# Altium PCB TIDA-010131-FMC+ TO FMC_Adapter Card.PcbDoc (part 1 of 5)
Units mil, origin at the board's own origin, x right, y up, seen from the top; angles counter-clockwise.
Board outline 2874.02 x 2362.2 mil, 12 copper layers (L1_Top Layer, L2_GND, L3_GND, L4_Signal layer1, L5_GND, L6_Signal Layer2, L7_GND, L8_Signal Layer3, L9_GND, L10_Signal Layer4, L11_GND, L12_Bottom Layer), stack 65.6 mil thick; 64 components, 219 nets, 2252 pads, 791 vias.
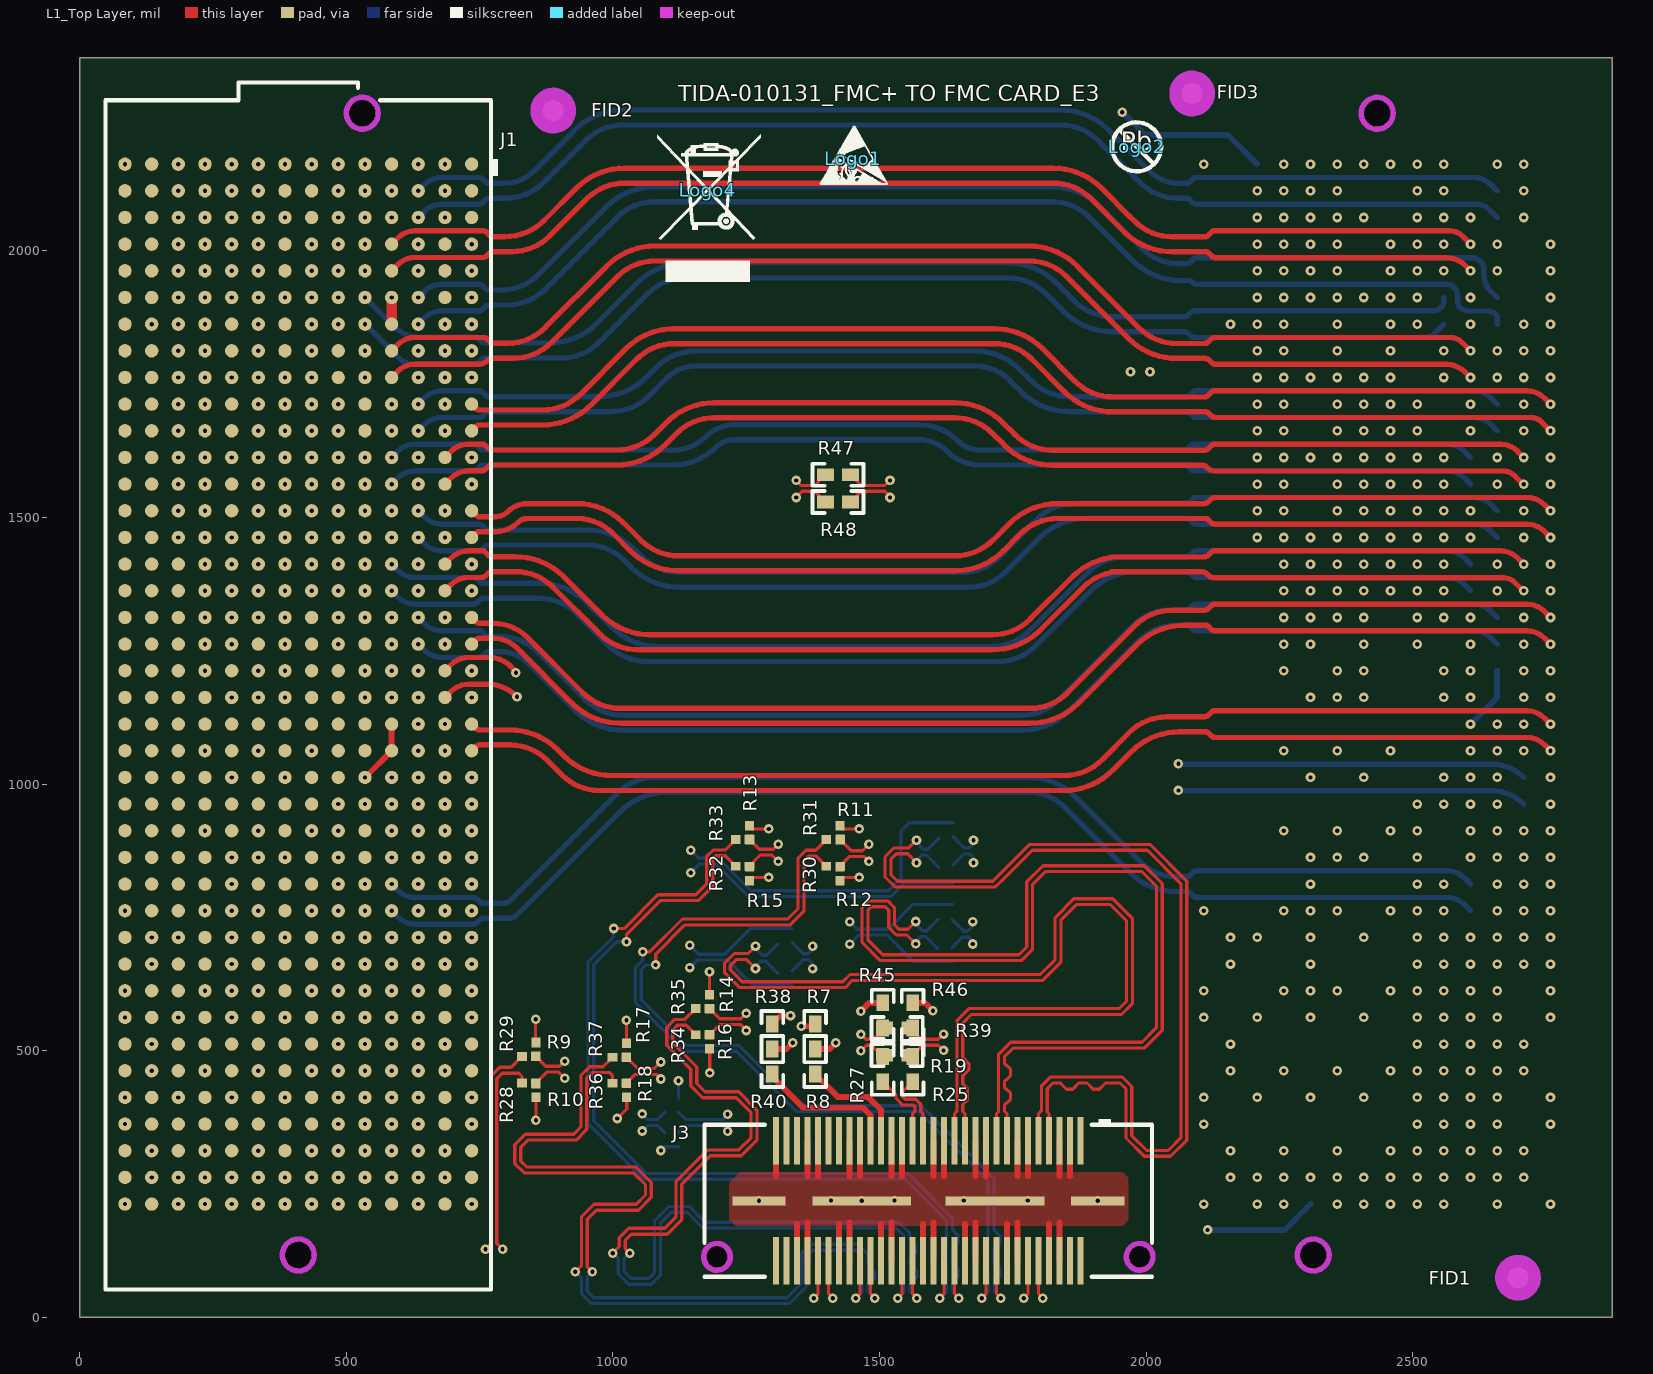
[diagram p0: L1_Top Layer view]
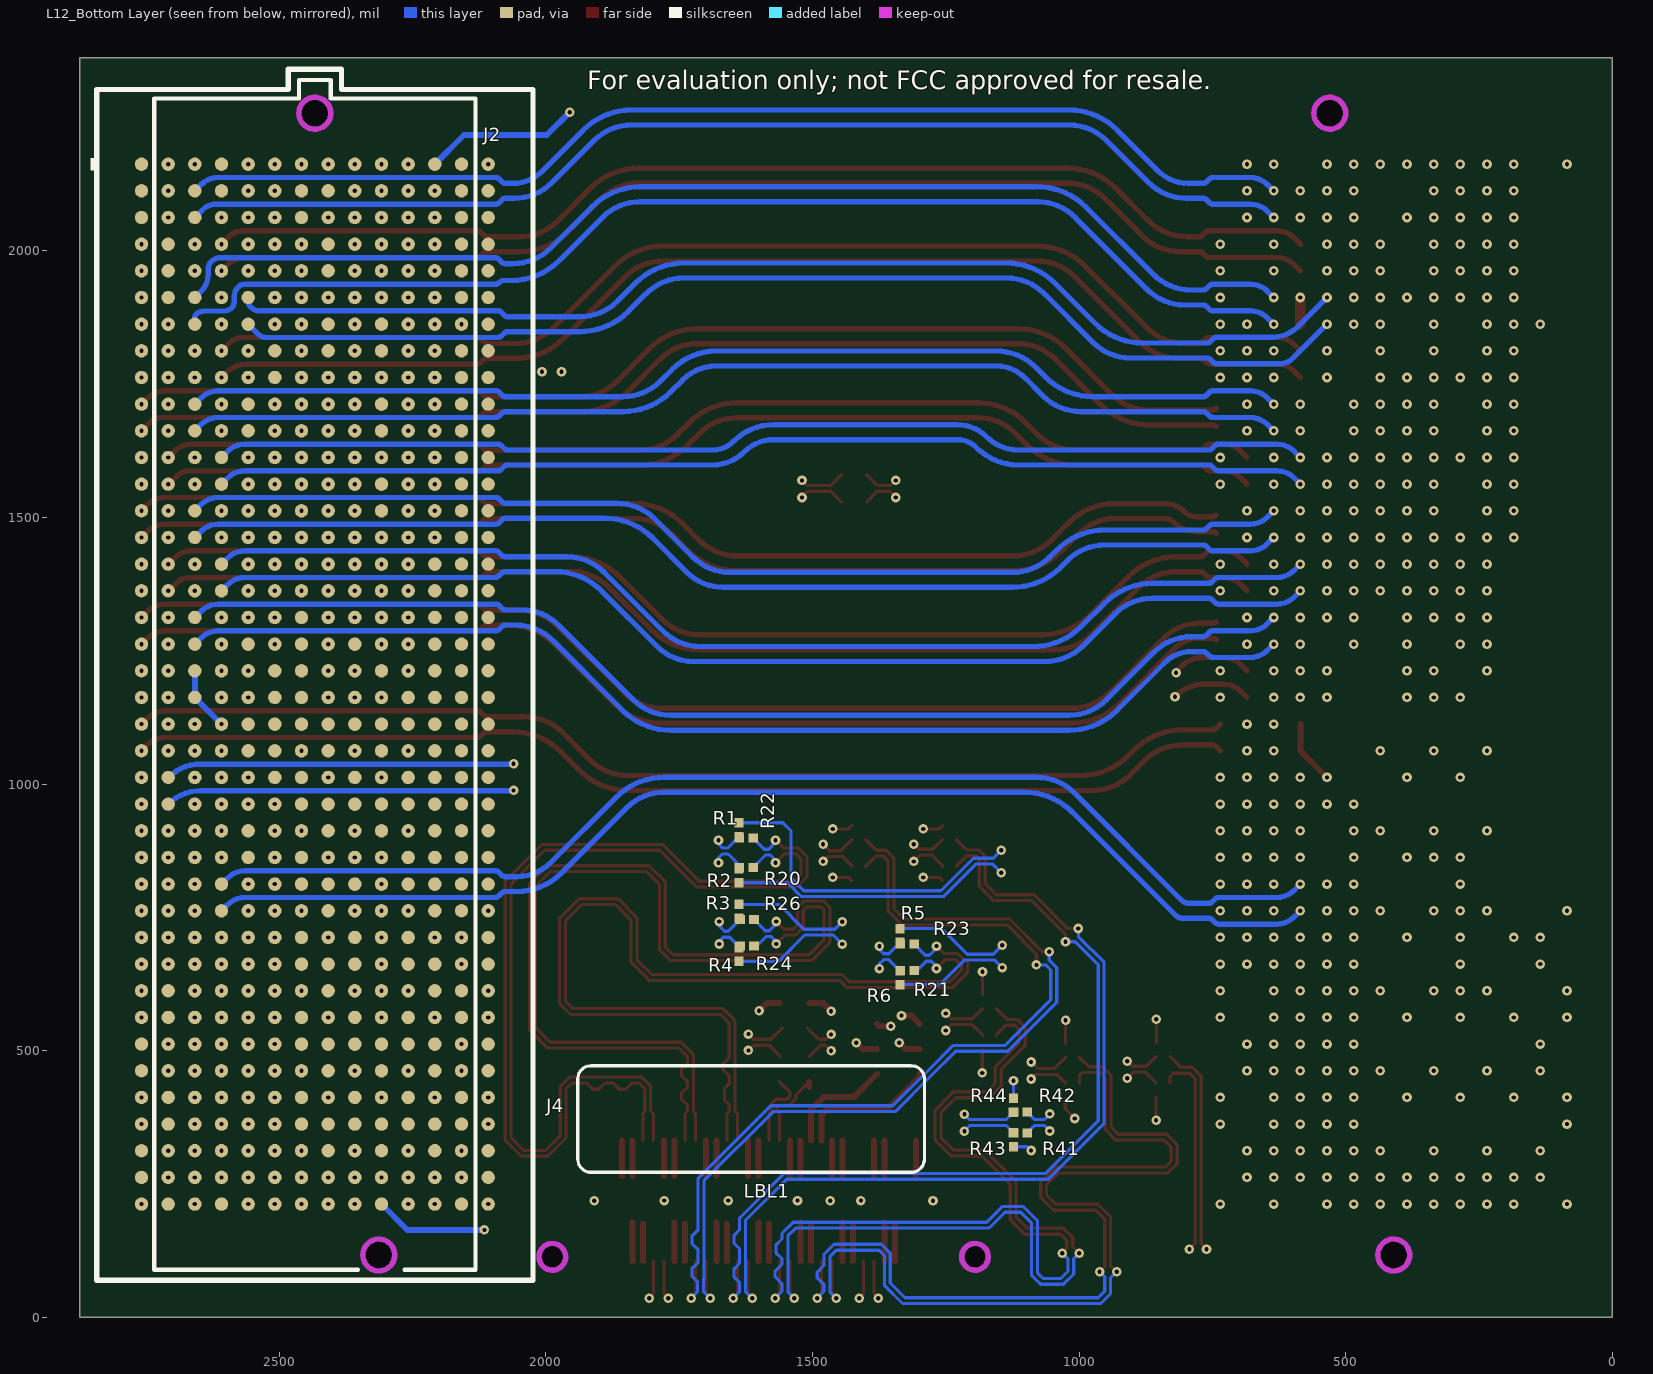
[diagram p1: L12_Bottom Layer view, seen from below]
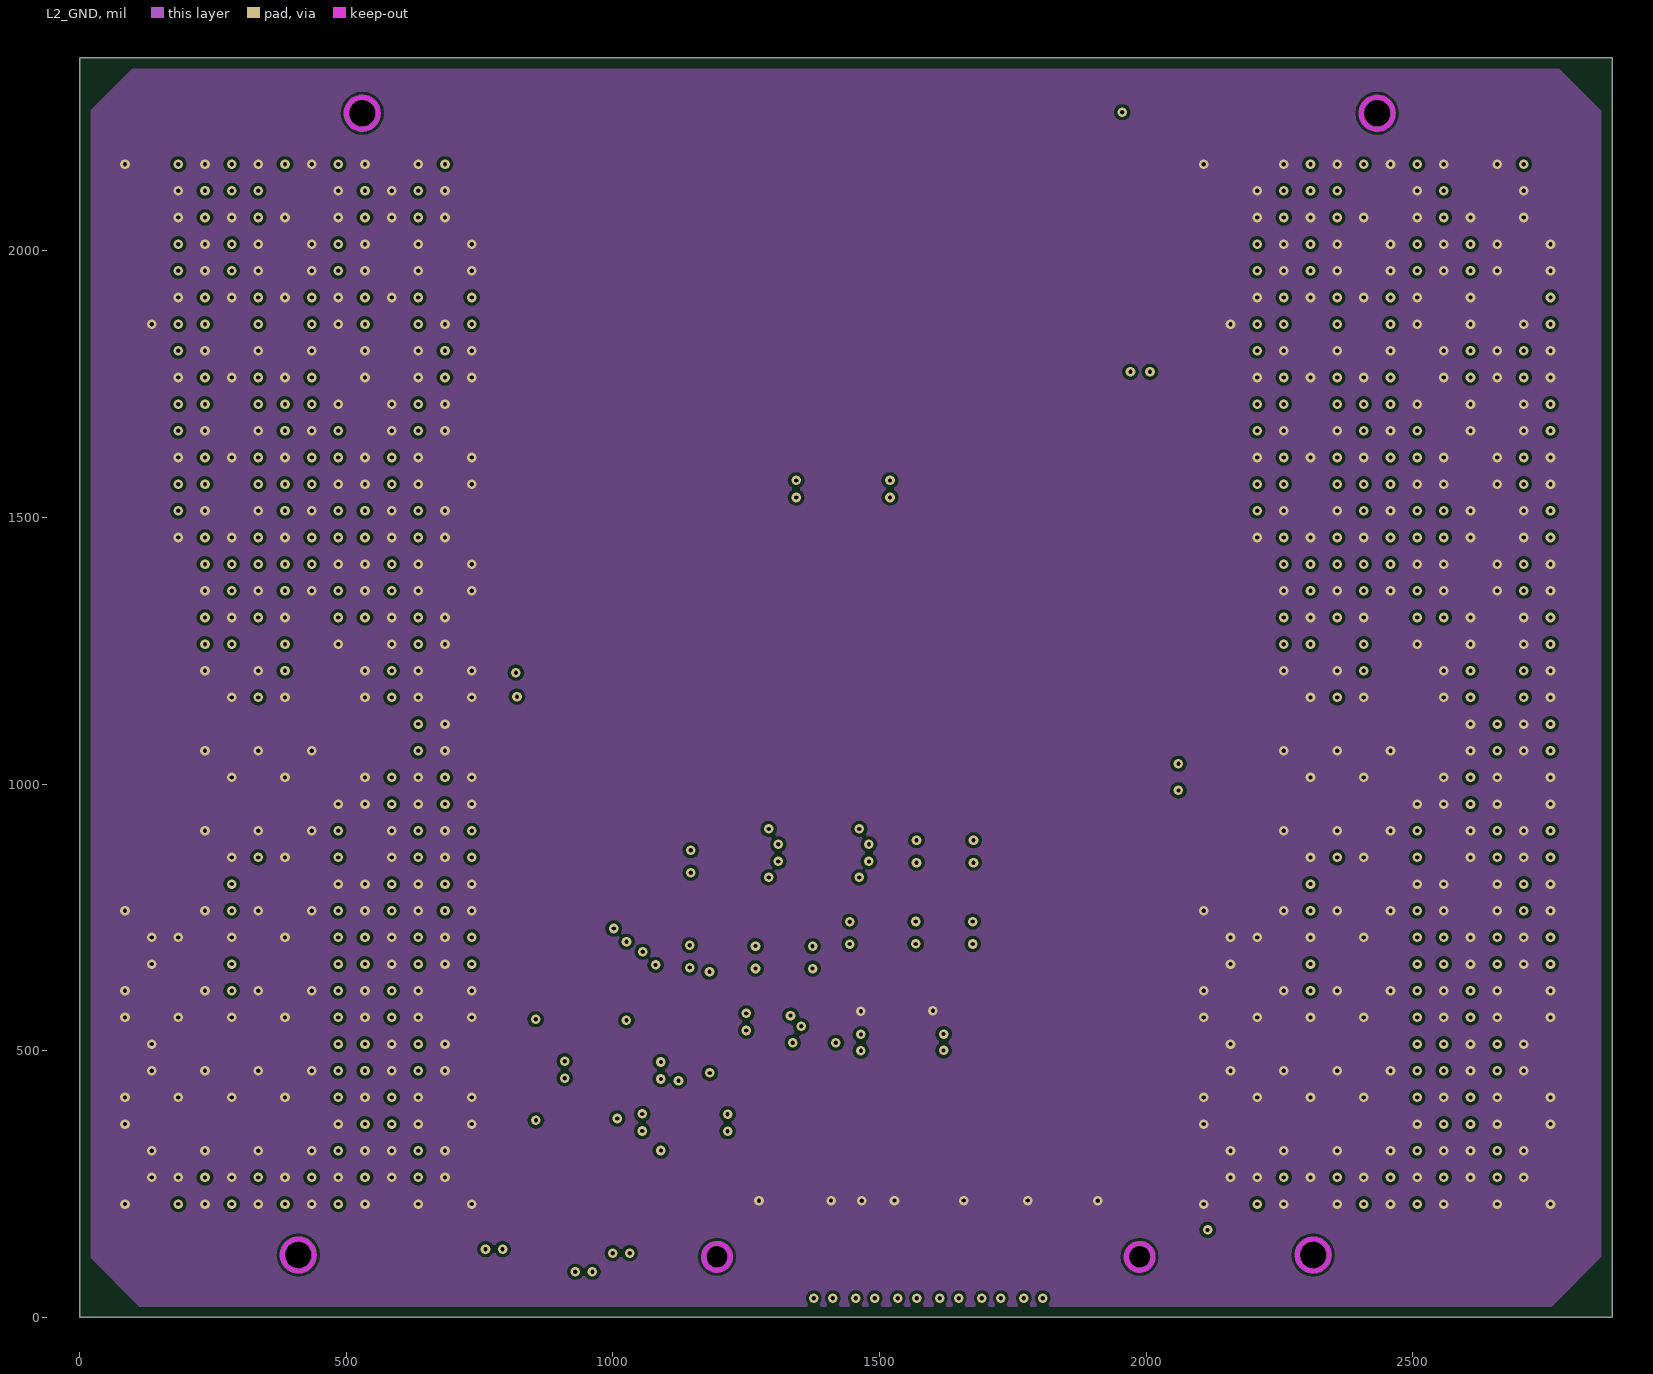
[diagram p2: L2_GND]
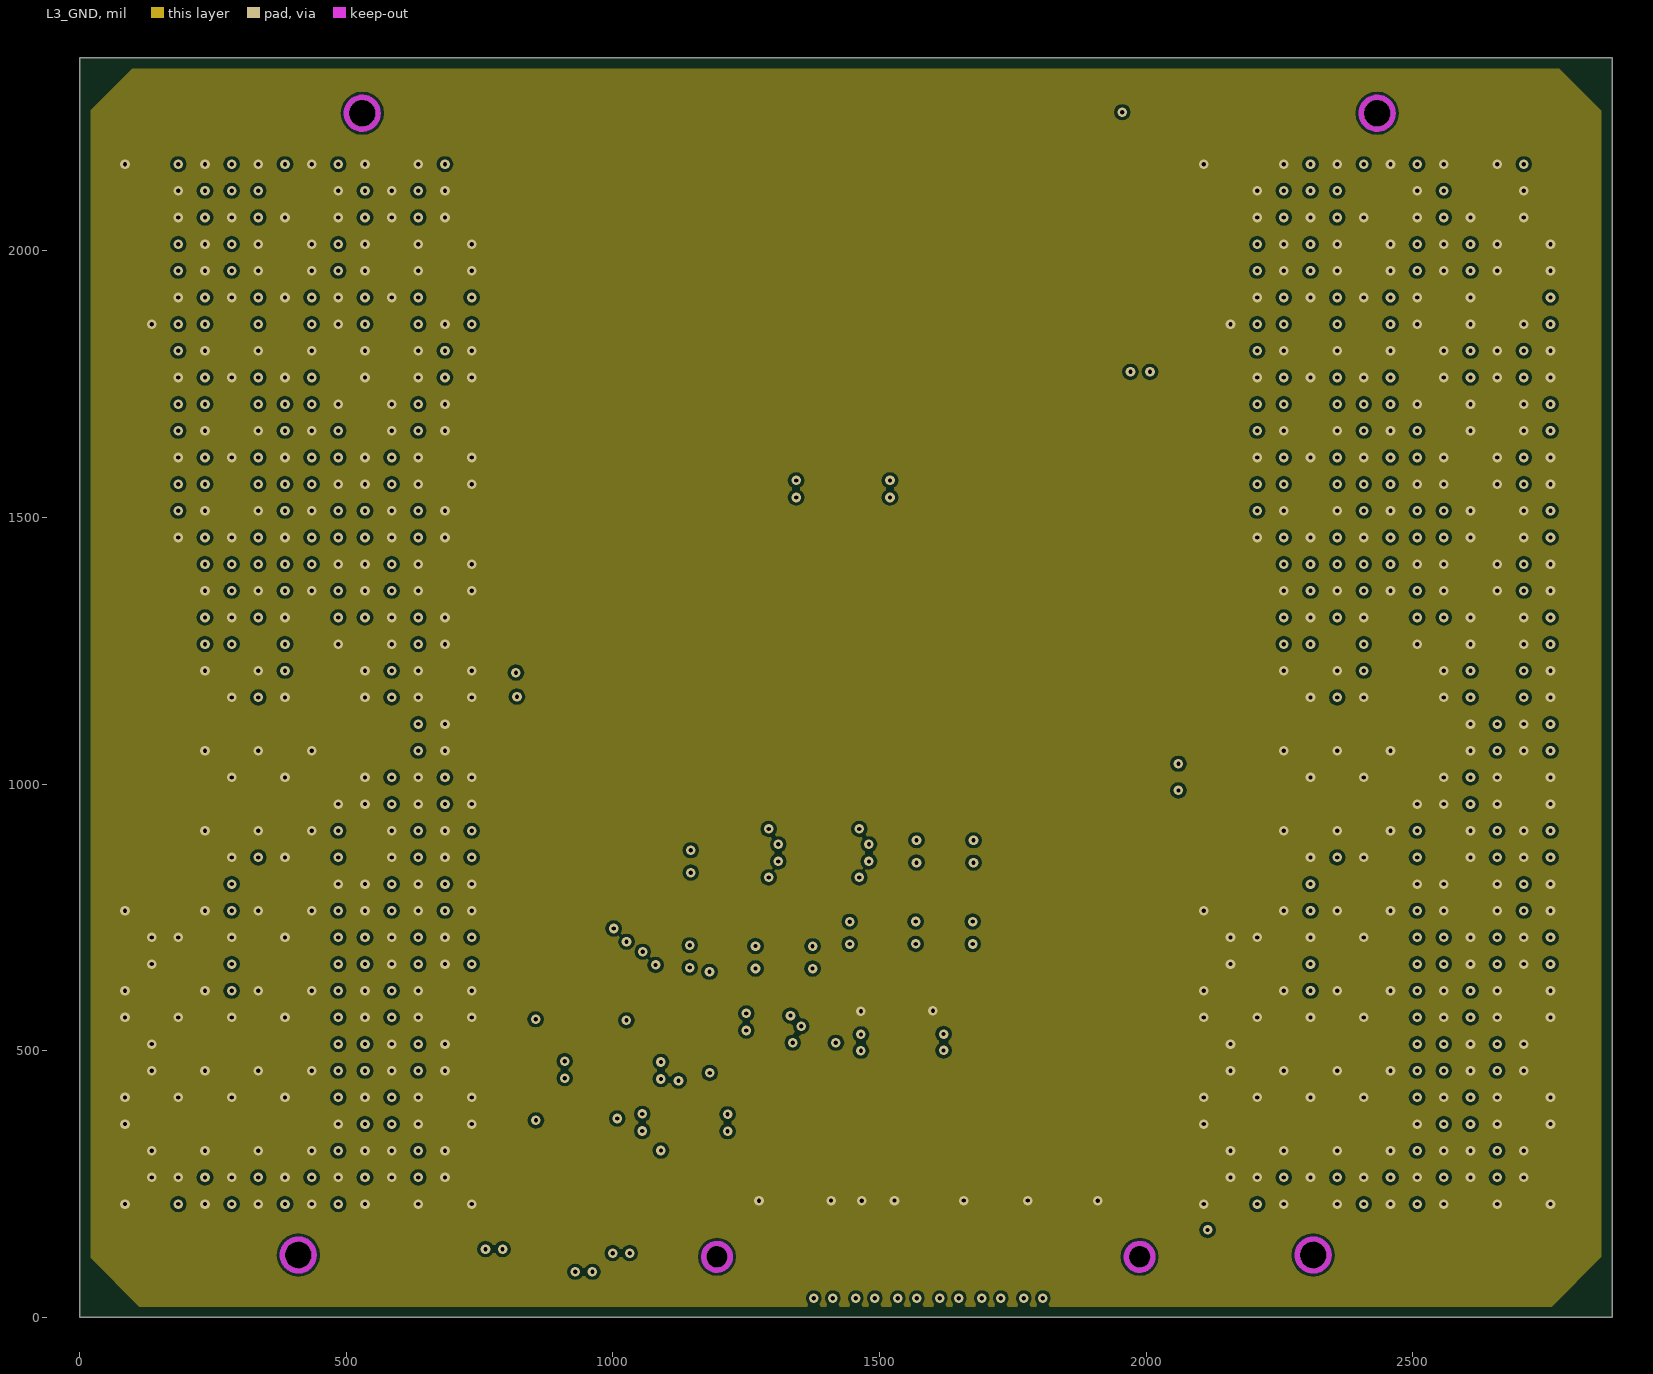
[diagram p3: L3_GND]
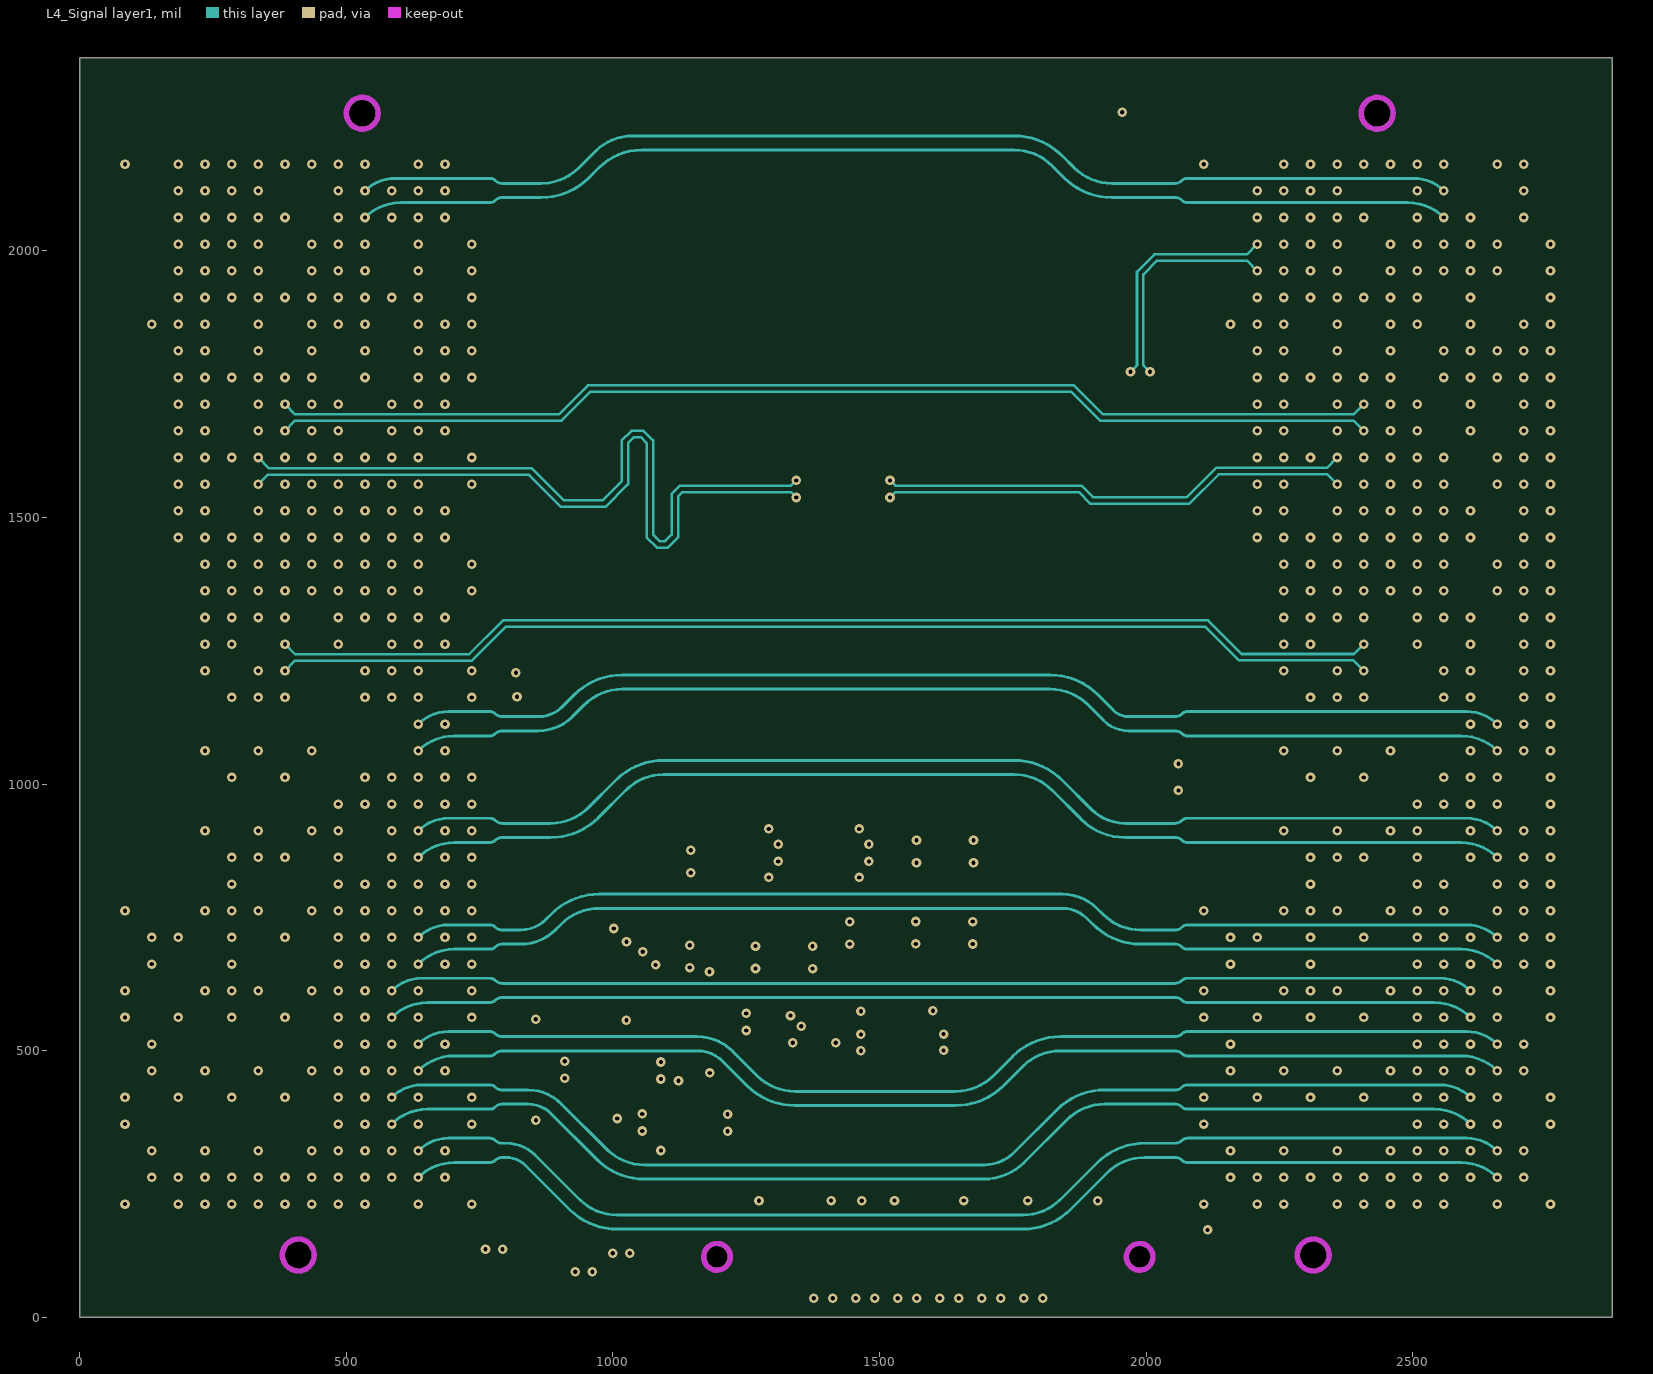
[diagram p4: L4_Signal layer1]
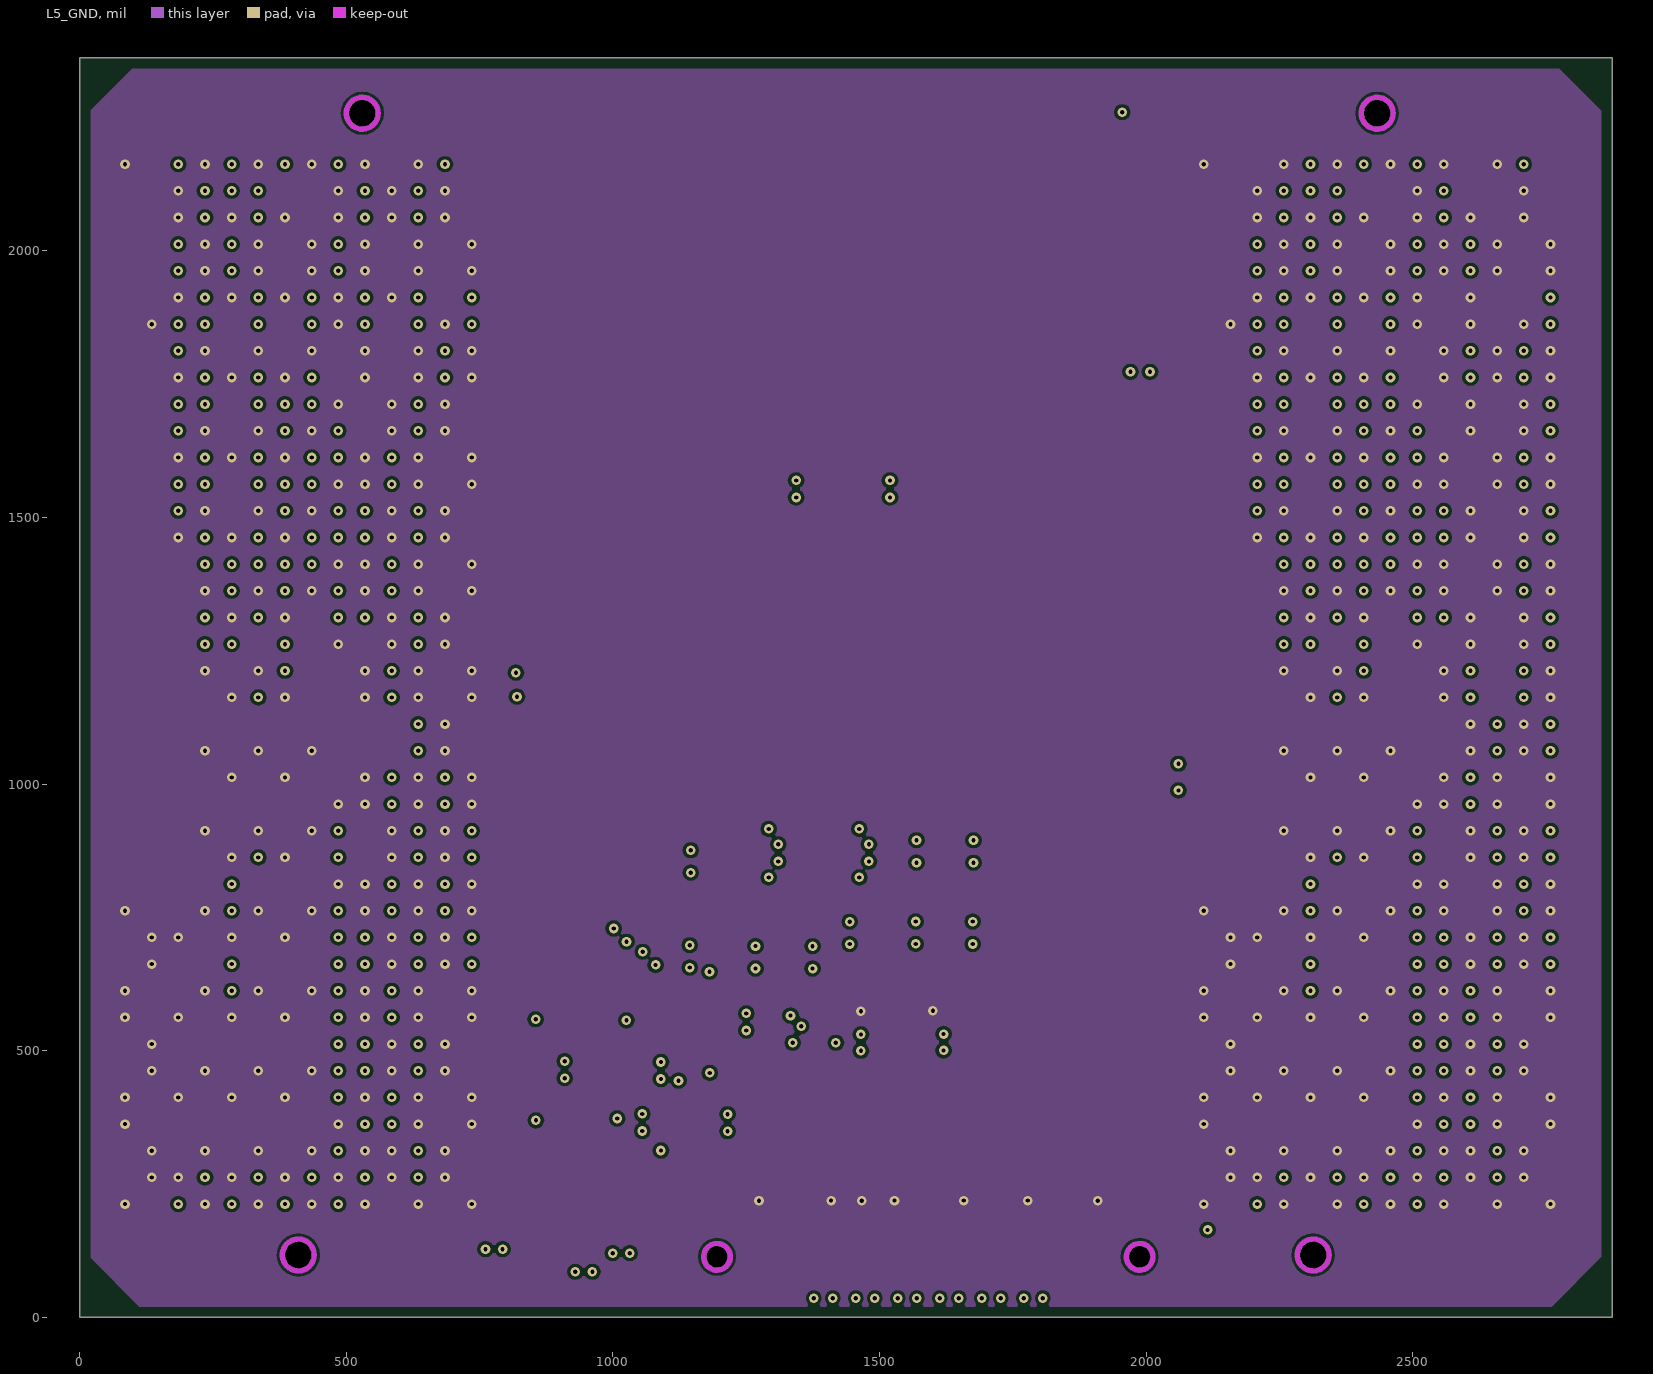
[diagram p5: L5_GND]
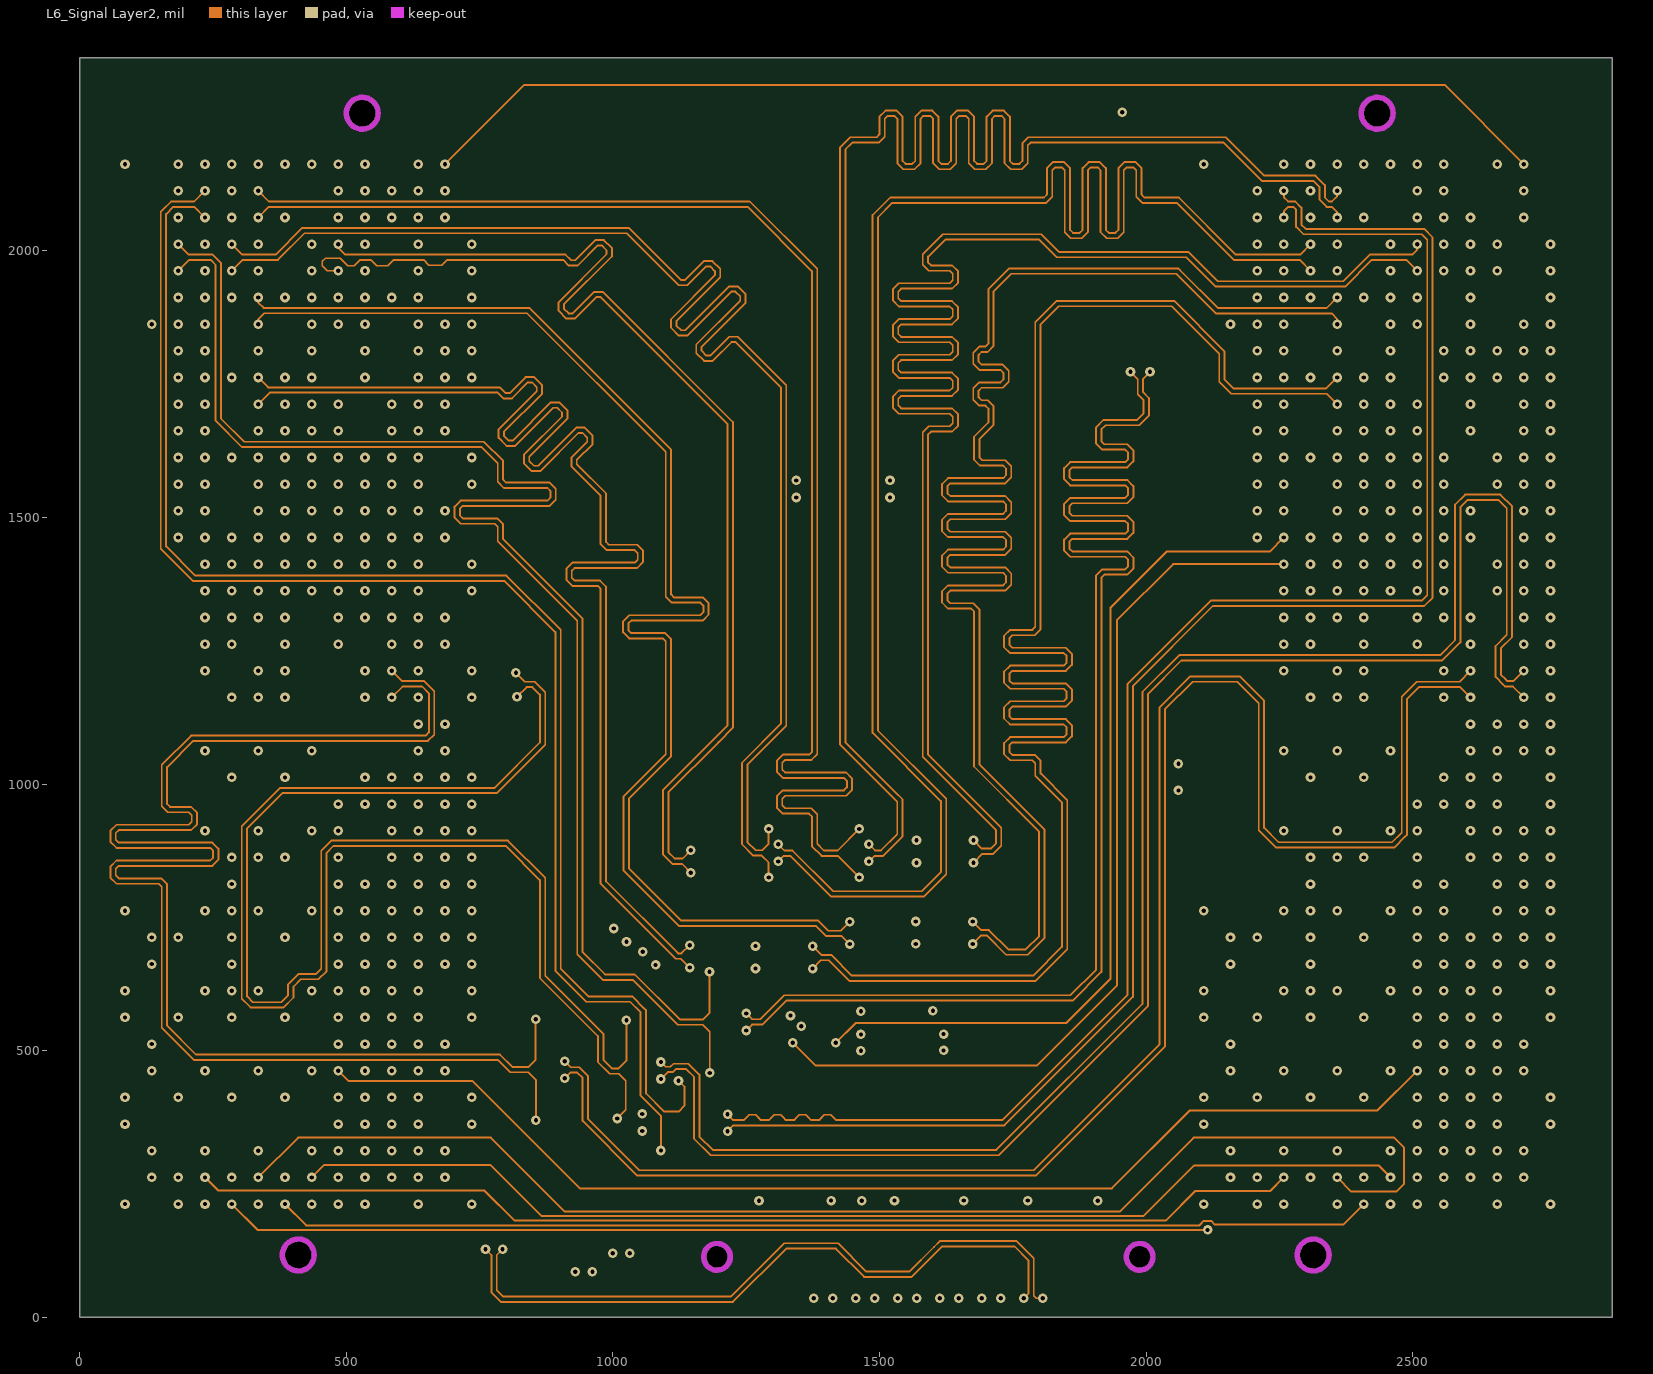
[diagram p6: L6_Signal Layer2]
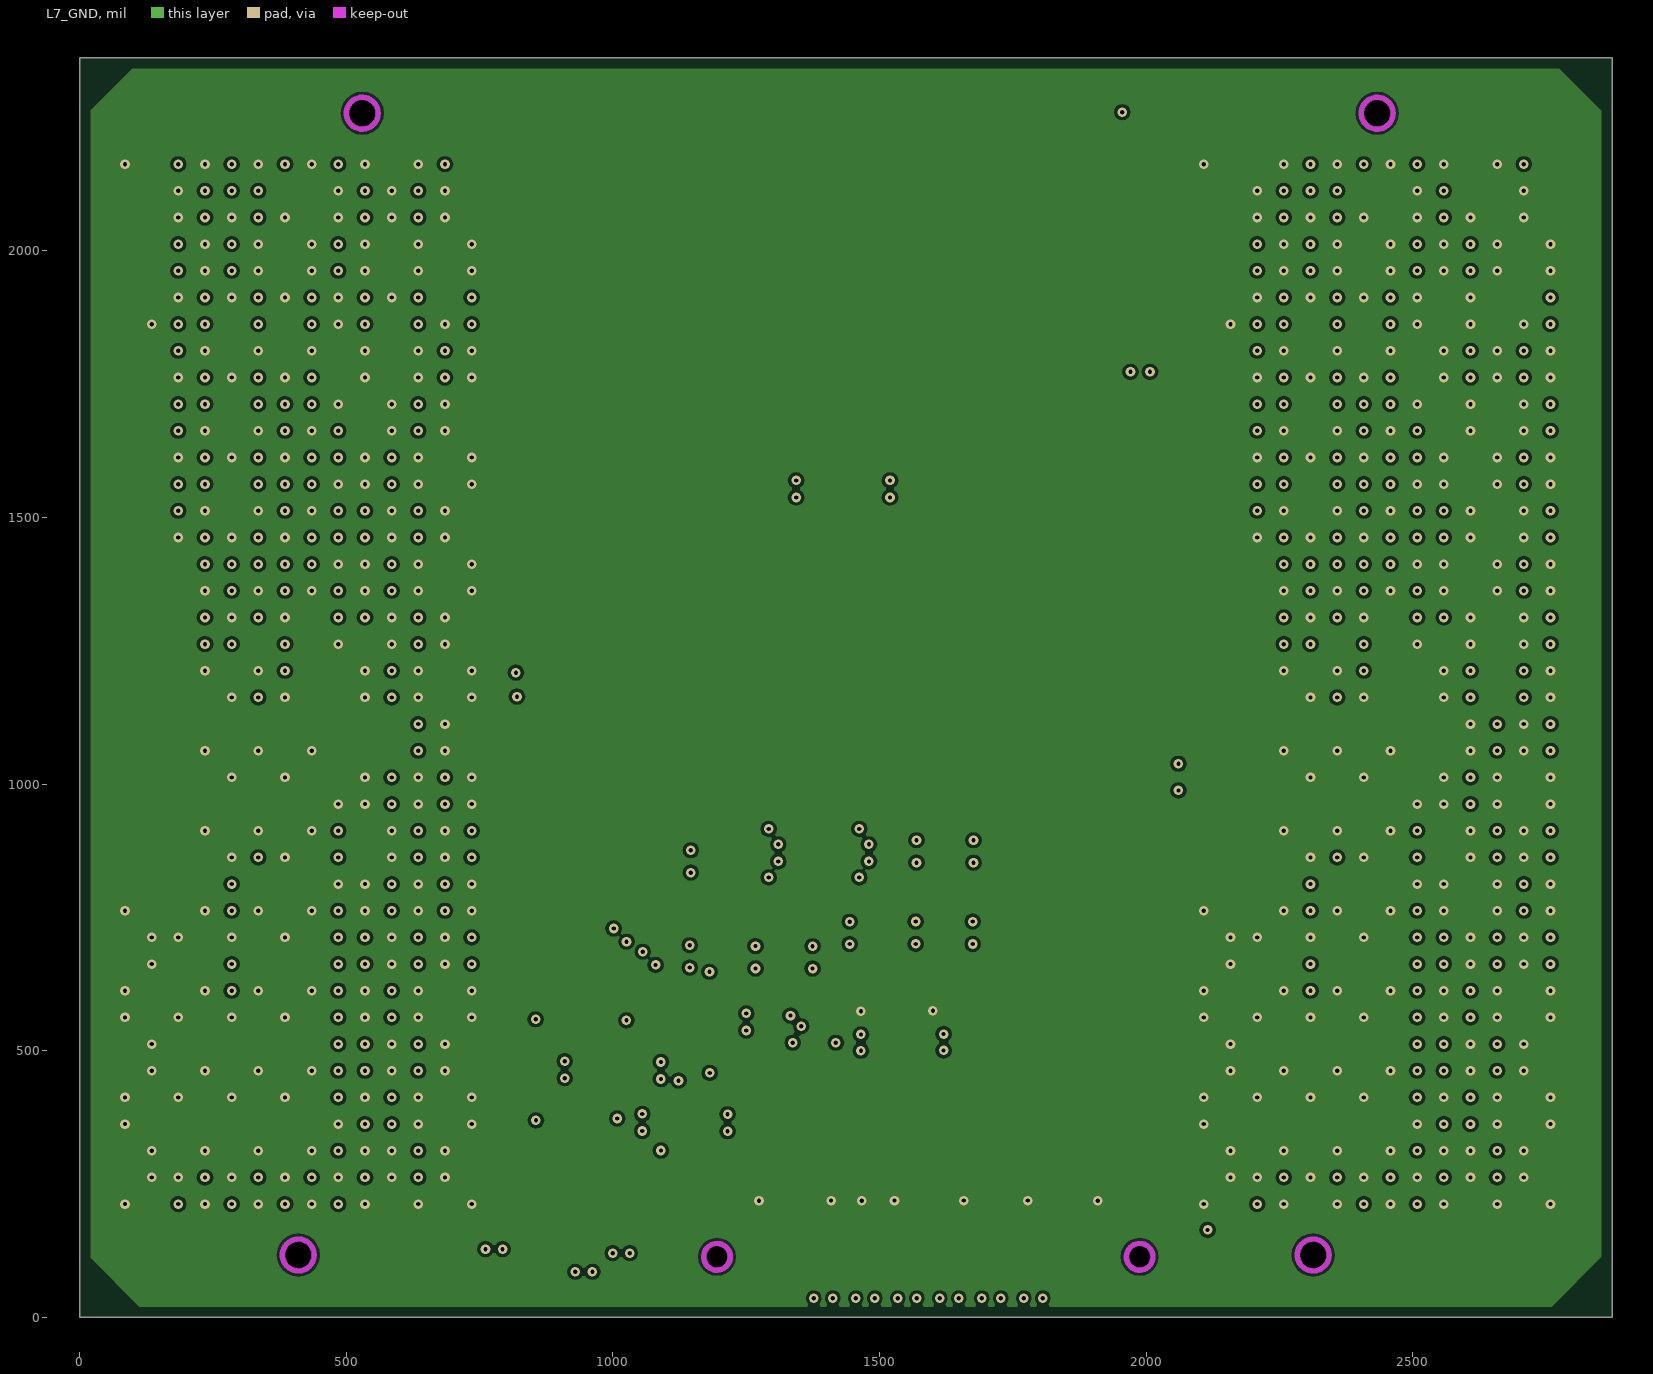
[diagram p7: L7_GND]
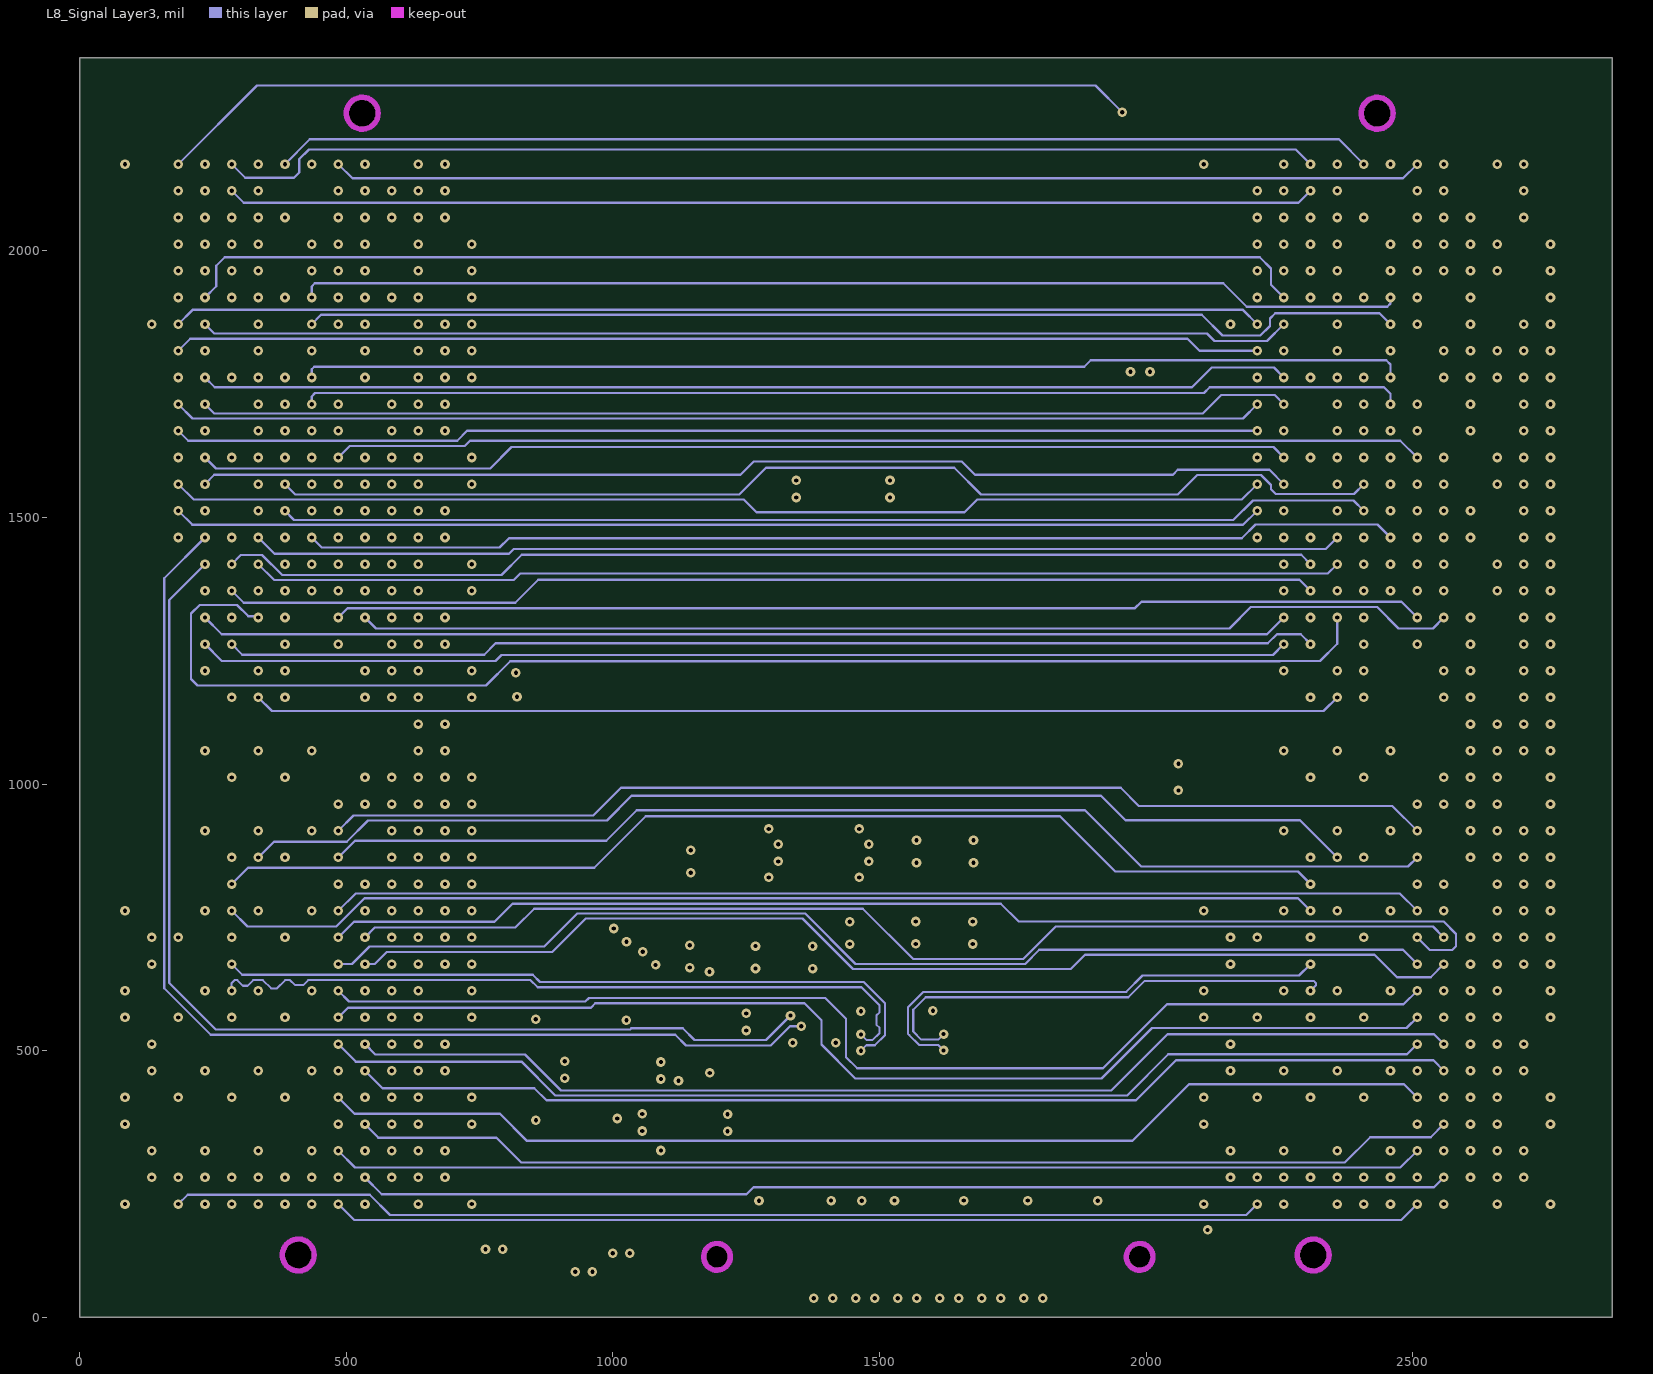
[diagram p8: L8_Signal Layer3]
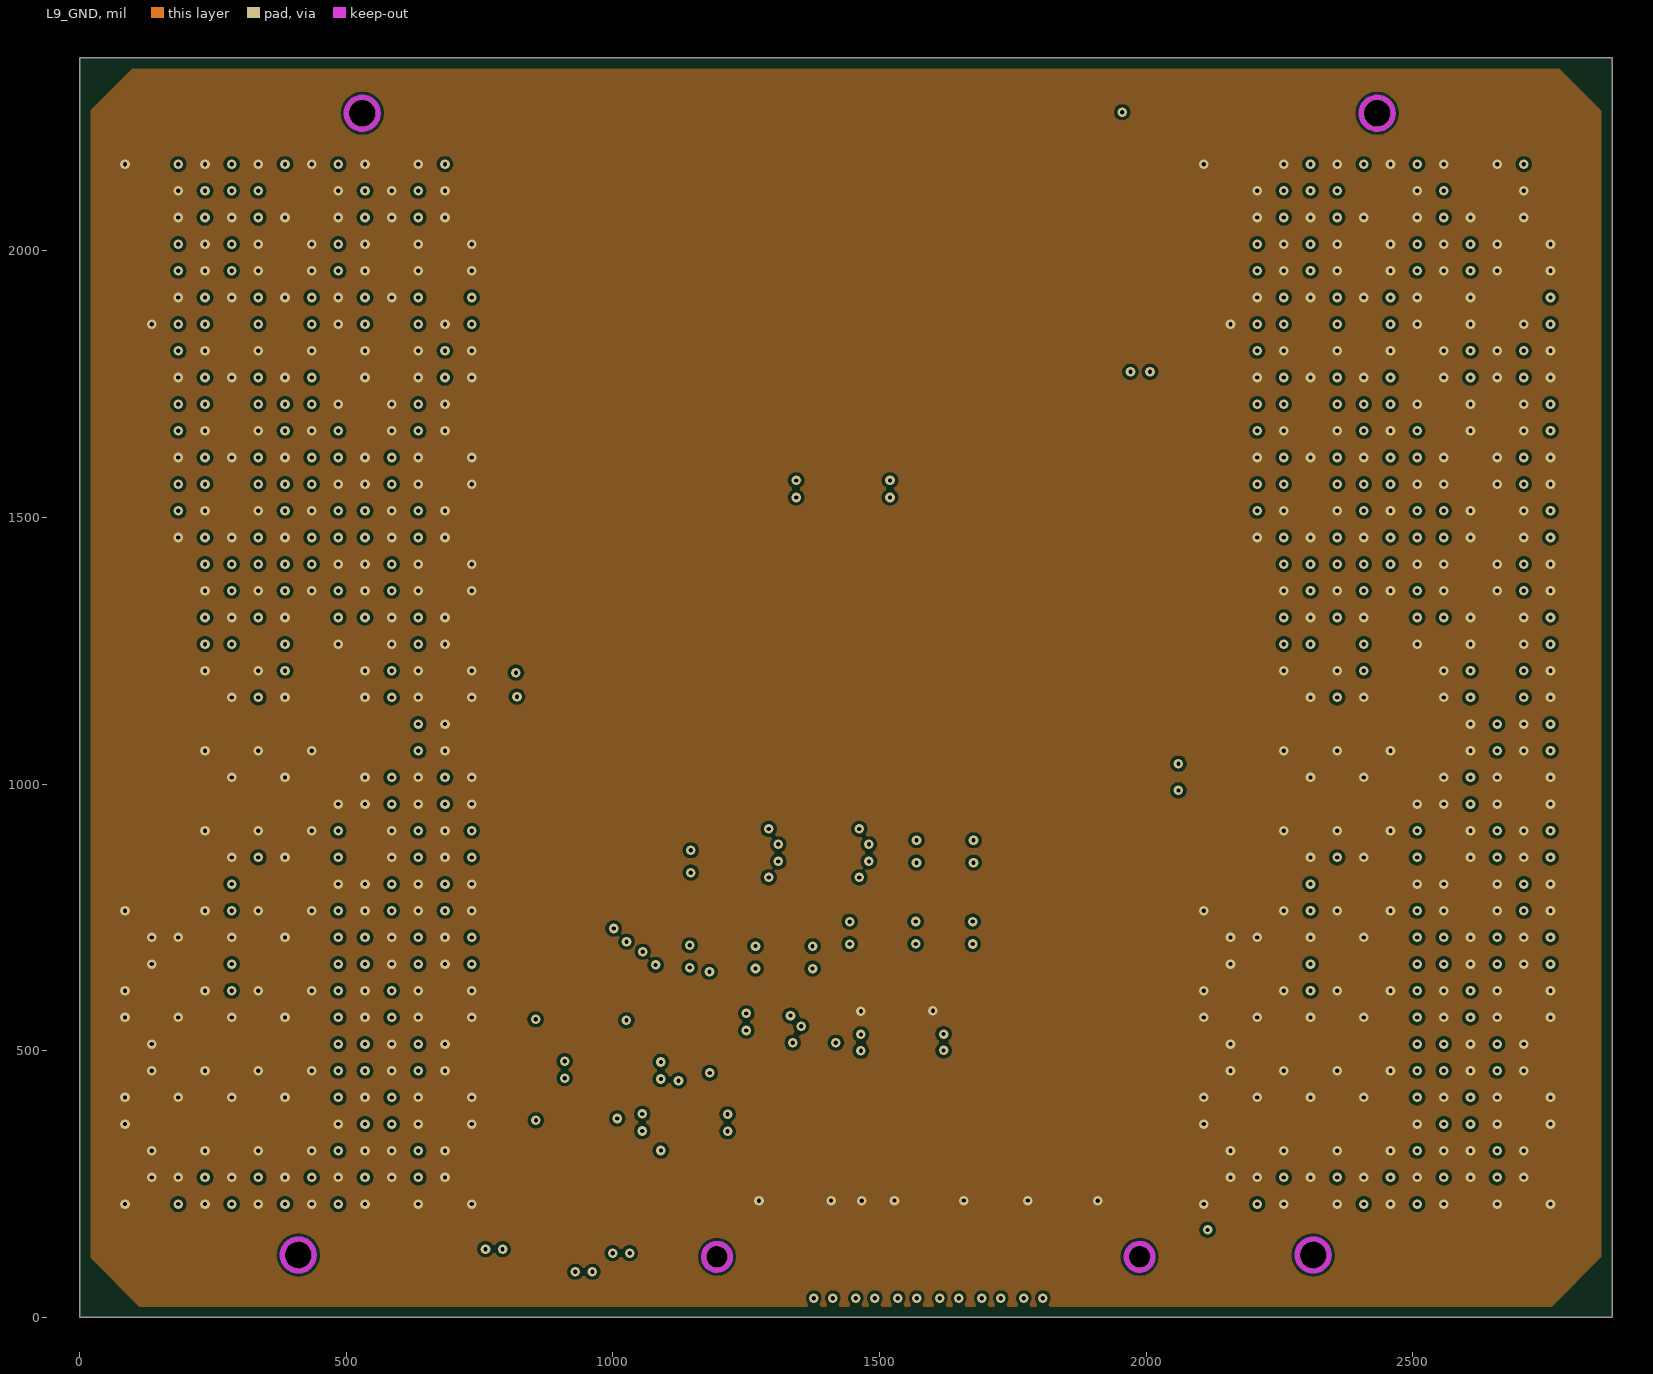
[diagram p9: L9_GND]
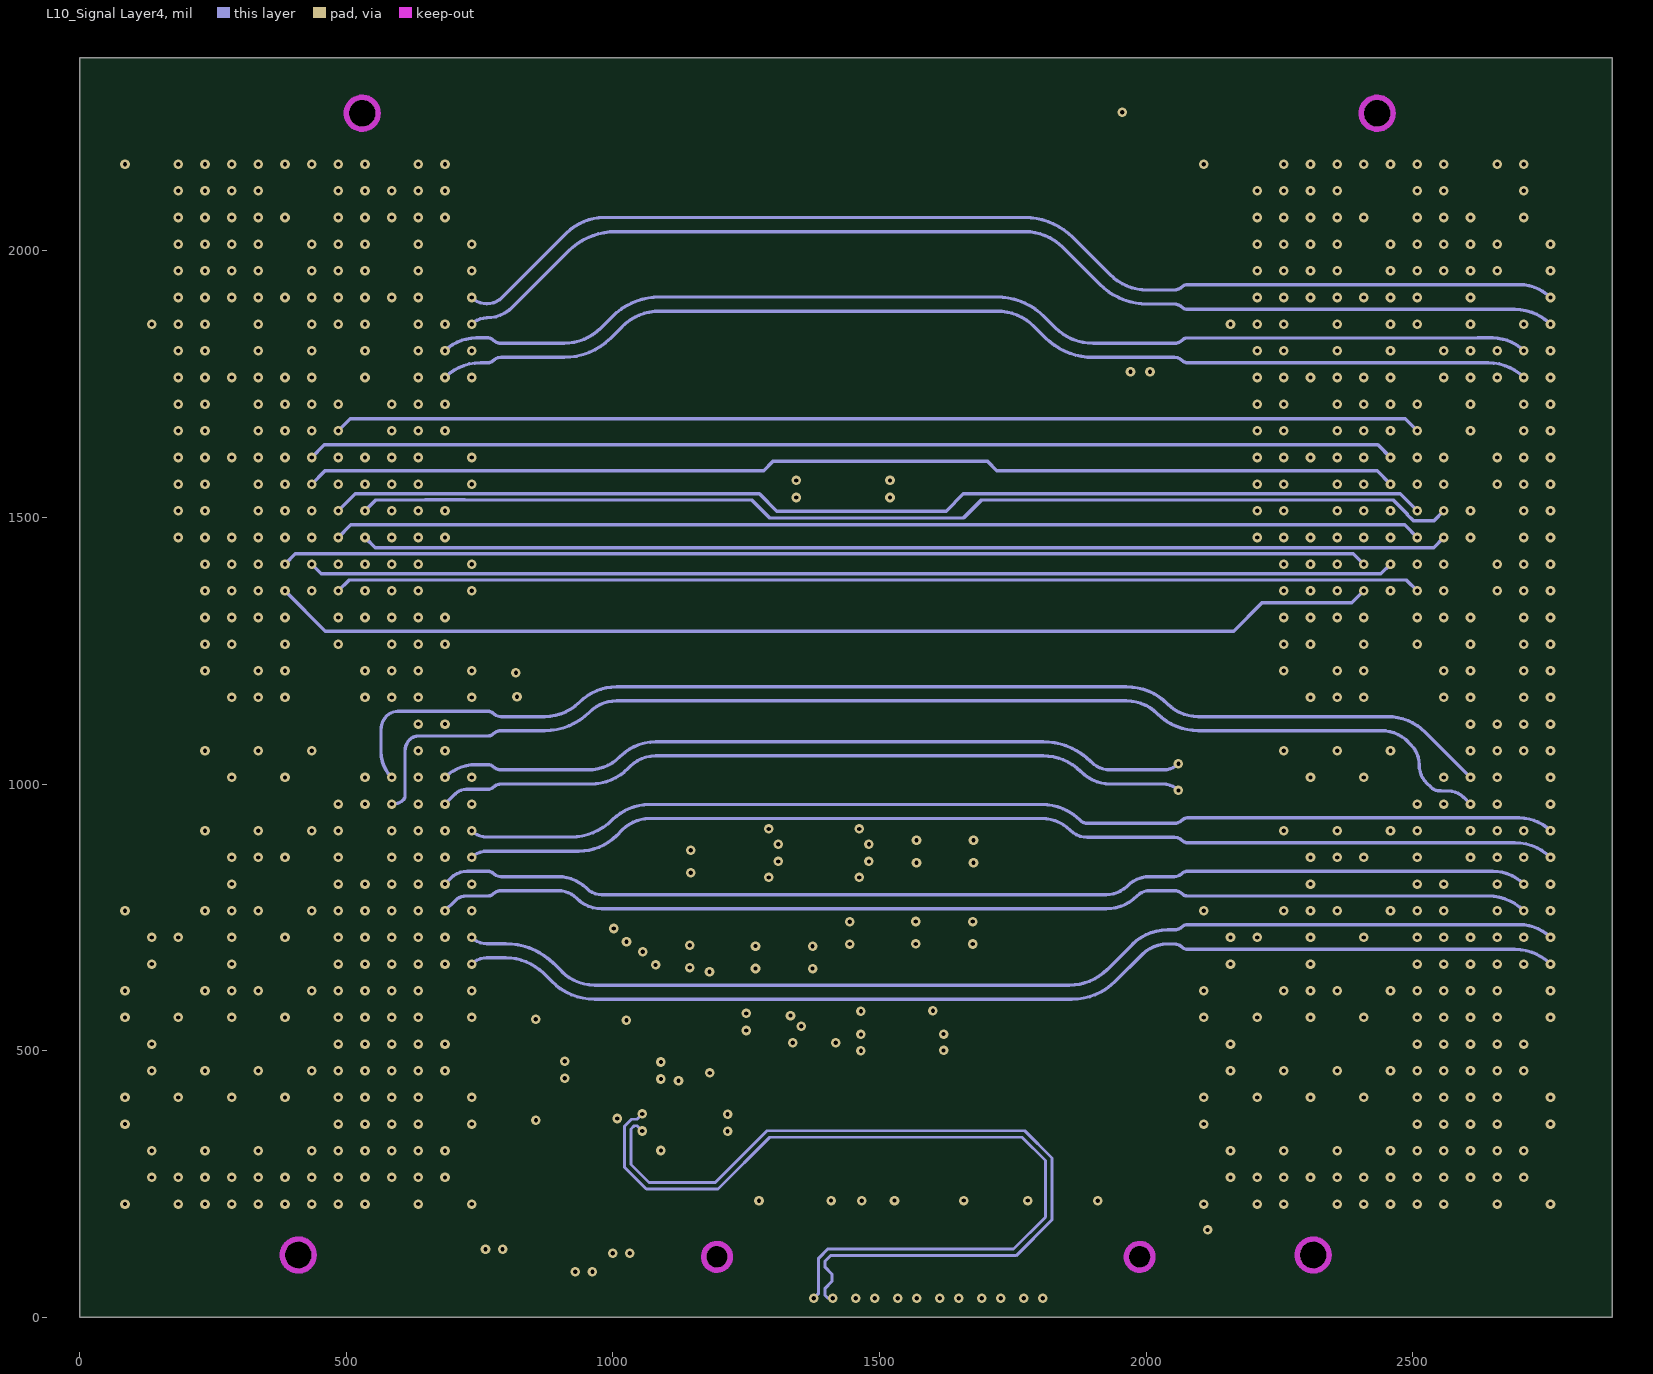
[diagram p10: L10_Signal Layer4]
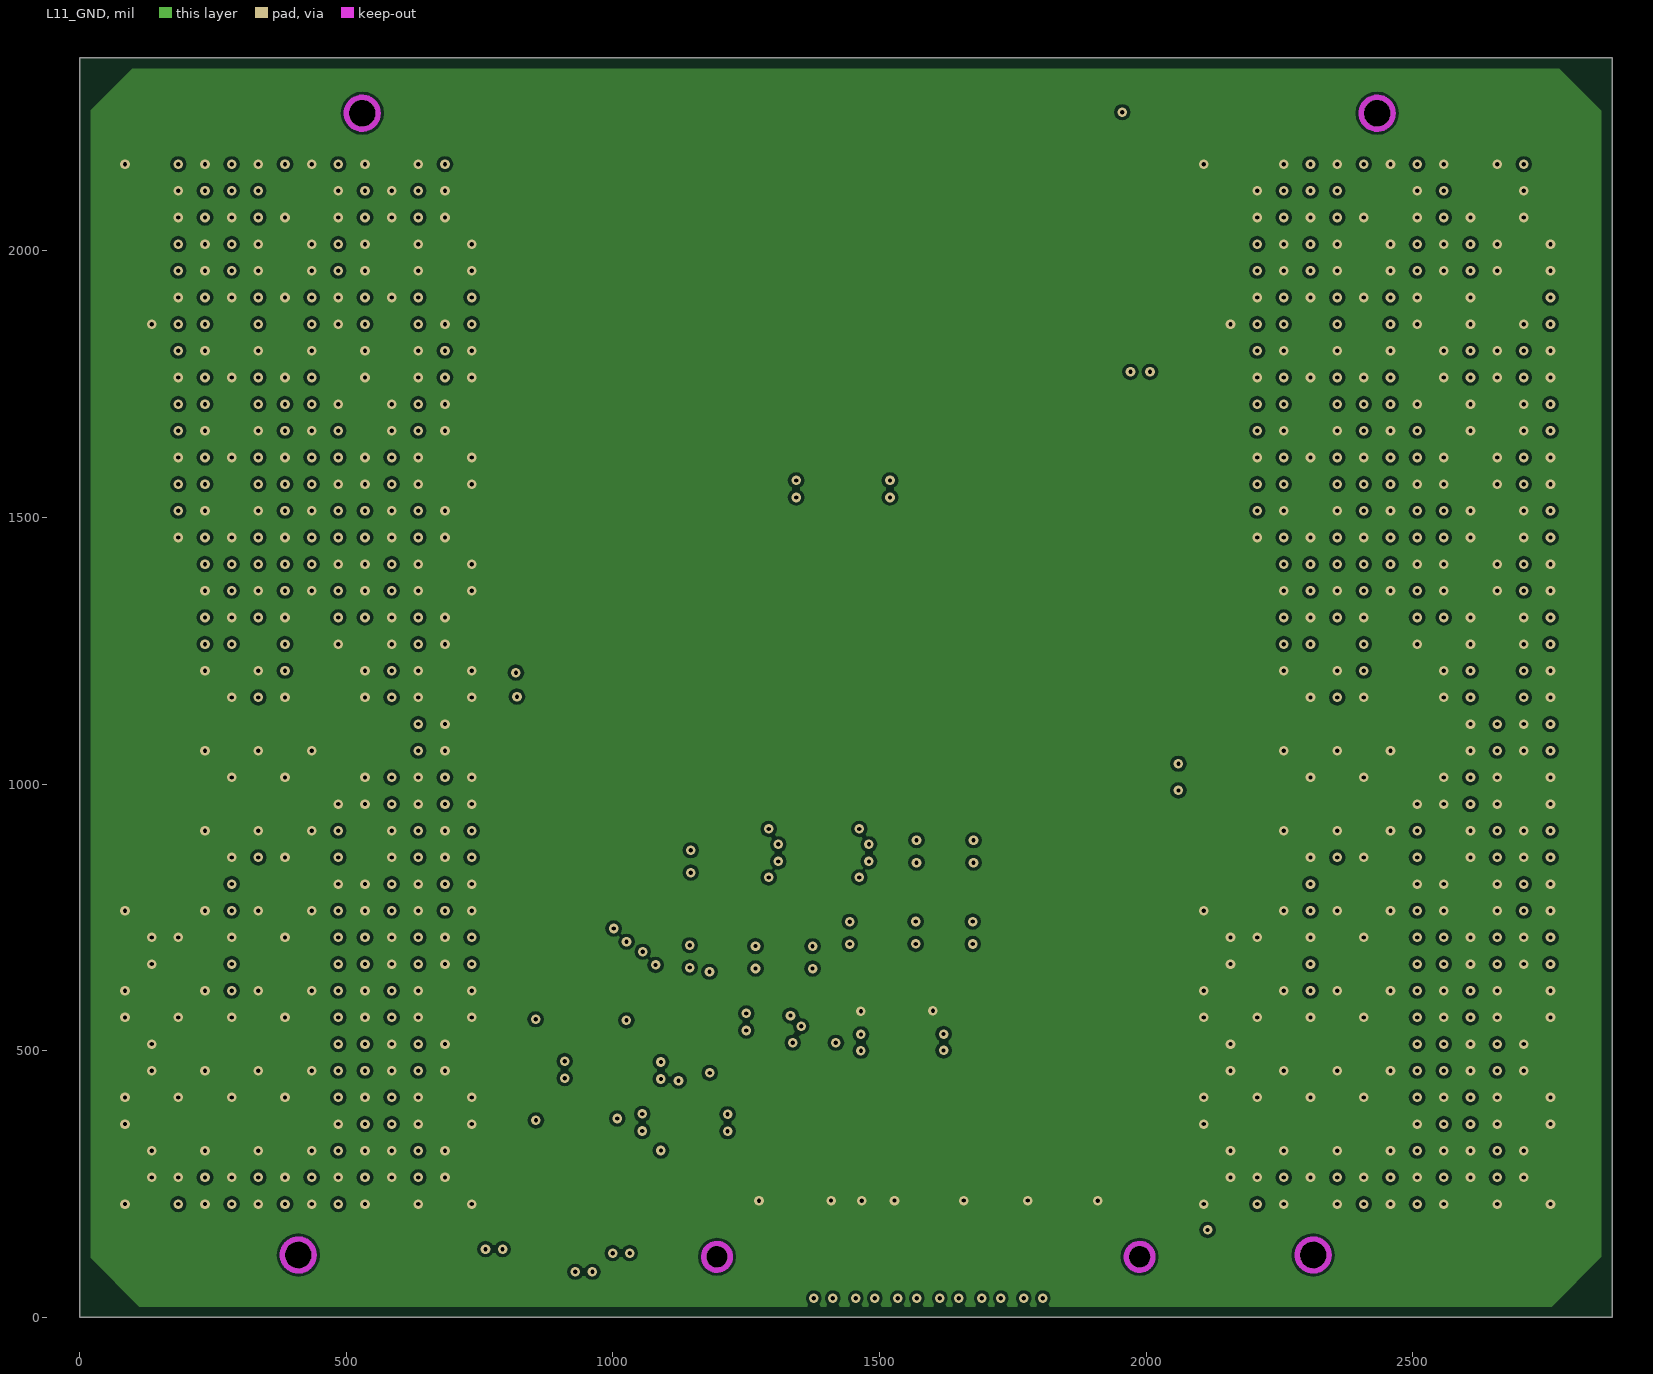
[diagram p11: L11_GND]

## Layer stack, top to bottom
Top Solder: solder mask 0.4, Solder Resist, Dk 3.5
L1_Top Layer: signal copper 2
Dielectric1: core 5.6, R-5670K, Dk 3.22
L2_GND: signal copper 0.6
Dielectric 2: prepreg 5, R-5775K, Dk 3.58
L3_GND: signal copper 0.6
Dielectric 3: core 7.5, R-5670K, Dk 3.23
L4_Signal layer1: signal copper 0.6
Dielectric 4: prepreg 4, R-5775K, Dk 3.39
L5_GND: signal copper 0.6
Dielectric 5: core 4.2, R-5670K, Dk 3.18
L6_Signal Layer2: signal copper 0.6
Dielectric 6: prepreg 3, R-5775K, Dk 3.42
L7_GND: signal copper 0.6
Dielectric 7: core 4.2, R-5670K, Dk 3.18
L8_Signal Layer3: signal copper 0.6
Dielectric 8: prepreg 4, R-5775K, Dk 3.39
L9_GND: signal copper 0.6
Dielectric 9: core 7.5, R-5670K, Dk 3.23
L10_Signal Layer4: signal copper 0.6
Dielectric 10: prepreg 5, R-5775K, Dk 3.58
L11_GND: signal copper 0.6
Dielectric 11: core 5.6, R-5670K, Dk 3.22
L12_Bottom Layer: signal copper 2
Bottom Solder: solder mask 0.4, Solder Resist, Dk 3.5

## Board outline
0,0 2874.02,0 2874.02,2362.2 0,2362.2

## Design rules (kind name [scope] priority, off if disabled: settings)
AcuteAngle [All] p1: minimum=4.50000000000000E+0001 checktracksonly=FALSE
AssemblyTestPointUsage [All] p1: valid=2
BoardOutlineClearance [IsPolygon] p1: gap=20 ignorepadtopadclearanceinfootprint=FALSE
Clearance Clearance_viatotrack [IsVia vs IsTrack] p1: gap=6 ignorepadtopadclearanceinfootprint=FALSE except(0: Arc-Hole Track-Hole SMDPad-Hole THPad-Hole Via-Hole Fill-Hole Poly-Hole Region-Hole Text-Hole)
Clearance Clearance_Poly [InPolygon vs InPolygon] p2: gap=25 ignorepadtopadclearanceinfootprint=FALSE except(0: Arc-Hole Track-Hole SMDPad-Hole THPad-Hole Via-Hole Fill-Hole Poly-Hole Region-Hole Text-Hole)
Clearance "Clearance_Poly to All" [IsVia or IsTrack or IsSMTPin or IsThruPin vs InPolygon] p3: gap=12 ignorepadtopadclearanceinfootprint=FALSE except(0: Arc-Hole Track-Hole SMDPad-Hole THPad-Hole Via-Hole Fill-Hole Poly-Hole Region-Hole Text-Hole; 6: Via-Poly)
Clearance "Via to Via" [IsVia vs IsVia] p4: gap=6.6 ignorepadtopadclearanceinfootprint=FALSE except(0: Arc-Hole Track-Hole SMDPad-Hole THPad-Hole Via-Hole Fill-Hole Poly-Hole Region-Hole Text-Hole)
Clearance "Via 2 SMD PAD" [IsVia vs IsSMTPin] p5: gap=6.6 ignorepadtopadclearanceinfootprint=FALSE except(0: Arc-Hole Track-Hole SMDPad-Hole THPad-Hole Via-Hole Fill-Hole Poly-Hole Region-Hole Text-Hole)
Clearance [All] p6: gap=5 ignorepadtopadclearanceinfootprint=FALSE except(0: Arc-Arc Arc-Track Arc-SMDPad Arc-THPad Arc-Hole Track-Hole SMDPad-Hole THPad-Hole Via-Hole Fill-Hole Poly-Hole Region-Hole Text-Hole)
ComponentClearance ComponentClearance_Shunt [InComponentClass('Header') vs InComponentClass('Shunt')] p1: gap=0 collisioncheckmode=3 verticalgap=0 showdistances=FALSE
ComponentClearance ComponentClearance_Logo [InComponentClass('Logo')] p2: gap=50 collisioncheckmode=3 verticalgap=10 showdistances=FALSE
ComponentClearance ComponentClearance_ScrewToNut [(HasFootprint('NY PMS 440 0025 PH')) vs (HasFootprint('Keystone_1902C'))] p3: gap=5 collisioncheckmode=3 verticalgap=10 showdistances=FALSE
ComponentClearance ComponentClearance_MountingHoles [InComponentClass('Mounting Holes')] p4: gap=250 collisioncheckmode=3 verticalgap=100000 showdistances=FALSE
ComponentClearance ComponentClearance_SmallPassives [HasFootprint('0201*') or HasFootprint('0402*') or HasFootprint('0508') or HasFootprint('0603*') or HasFootprint('0612') or HasFootprint('0805*') or HasFootprint('0815*') or HasFootprint('0830*') or HasFootprint('1206*') or HasFootprint('1210*') or HasFootprint('1808*') or HasFootprint('1812*') or HasFootprint('1825*') or HasFootprint('2010*') or HasFootprint('2220*') or HasFootprint('2225*') or HasFootprint('2512*') or HasFootprint('2728*') or HasFootprint('3518*') vs HasFootprint('0201*') or HasFootprint('0402*') or HasFootprint('0508') or HasFootprint('0603*') or HasFootprint('0612') or HasFootprint('0805*') or HasFootprint('0815*') or HasFootprint('0830*') or HasFootprint('1206*') or HasFootprint('1210*') or HasFootprint('1808*') or HasFootprint('1812*') or HasFootprint('1825*') or HasFootprint('2010*') or HasFootprint('2220*') or HasFootprint('2225*') or HasFootprint('2512*') or HasFootprint('2728*') or HasFootprint('3518*')] p5: gap=20 collisioncheckmode=3 verticalgap=10 showdistances=FALSE
ComponentClearance ComponentClearance_THtoSMT [IsThruComponent vs IsSMTComponent] p6: gap=100 collisioncheckmode=3 verticalgap=30 showdistances=FALSE
ComponentClearance ComponentClearance_THtoTH [IsThruComponent vs IsThruComponent] p7: gap=118.11 collisioncheckmode=3 verticalgap=30 showdistances=FALSE
ComponentClearance [All] p8: gap=40 collisioncheckmode=3 verticalgap=10 showdistances=FALSE
DiffPairsRouting DiffPair_DiffPairsRouting [InDifferentialPairClass('100ohm')] p1: maxlimit=21.1 minlimit=5 mostfreqgap=20.1 toplayer_maxgap=18 toplayer_prefgap=18 toplayer_minwidth=6 toplayer_maxwidth=10 toplayer_prefwidth=10 midlayer1_mingap=0 midlayer1_maxgap=0 midlayer1_prefgap=0 midlayer1_minwidth=0 midlayer1_maxwidth=0 midlayer1_prefwidth=0 midlayer2_mingap=0 midlayer2_maxgap=0 midlayer2_prefgap=0 midlayer2_minwidth=0 midlayer2_maxwidth=0 midlayer2_prefwidth=0 midlayer3_mingap=6.5 midlayer3_maxgap=6.5 midlayer3_prefgap=6.5 midlayer3_minwidth=3.5 midlayer3_maxwidth=3.5 midlayer3_prefwidth=3.5 midlayer4_mingap=6 midlayer4_maxgap=6 midlayer4_prefgap=6 midlayer4_minwidth=4 midlayer4_maxwidth=4 midlayer4_prefwidth=4 midlayer5_mingap=0 midlayer5_maxgap=6 midlayer5_prefgap=0 midlayer5_minwidth=0 midlayer5_maxwidth=6 midlayer5_prefwidth=0 midlayer6_mingap=7.1 midlayer6_prefgap=21.1 midlayer6_minwidth=4.9 midlayer6_maxwidth=5.5 midlayer6_prefwidth=5.5 midlayer7_mingap=0 midlayer7_maxgap=0 midlayer7_prefgap=0 midlayer7_minwidth=0 midlayer7_maxwidth=0 midlayer7_prefwidth=0 midlayer8_mingap=0 midlayer8_maxgap=0 midlayer8_prefgap=0 midlayer8_minwidth=0 midlayer8_maxwidth=0 midlayer8_prefwidth=0 midlayer9_mingap=0 midlayer9_maxgap=0 midlayer9_prefgap=0 midlayer9_minwidth=0 midlayer9_maxwidth=0 midlayer9_prefwidth=0 midlayer10_mingap=6.7 midlayer10_maxgap=20.1 midlayer10_minwidth=5.5 midlayer10_maxwidth=6.3 midlayer10_prefwidth=6.3 bottomlayer_maxgap=18 bottomlayer_prefgap=18 bottomlayer_minwidth=6 bottomlayer_maxwidth=10 bottomlayer_prefwidth=10 maxuncoupledlength=1000
FabricationTestPointUsage TestPointUsage [All] p1: valid=2 allowmultiple=FALSE
FabricationTestpoint Testpoint [All] p1: side=3 testpointundercomponent=TRUE minsize=40 maxsize=100 preferedsize=60 minholesize=0 maxholesize=40 preferedholesize=32 testpointgrid=1 allowsidetop=TRUE allowsidebottom=TRUE usegrid=TRUE gridtolerance=0.01
FanoutControl Fanout_LCC [IsLCC] p1: bgadir=Out bgaviamode=Centered fanoutstyle=Auto fanoutdirection=Alternating viagrid=1 // Fanout_LCC (Default Rule)
FanoutControl Fanout_BGA [IsBGA] p2: bgadir=Out bgaviamode=Centered fanoutstyle=Auto fanoutdirection=Alternating viagrid=1 // Fanout_BGA (Default Rule)
FanoutControl Fanout_Default [All] p4: bgadir=Out bgaviamode=Centered fanoutstyle=Auto fanoutdirection=Alternating viagrid=1 // Fanout_Default (Default Rule)
FanoutControl Fanout_Small [(CompPinCount < 5)] p5: bgadir=Out bgaviamode=Centered fanoutstyle=Auto fanoutdirection=OutThenIn viagrid=1 // Fanout_Small (Default Rule)
HoleSize [All] p1: absolutevalues=TRUE maxlimit=251 minlimit=7.87 maxpercent=80.000 minpercent=20.000
MatchedLengths SYNCx [InNetClass('SYNCBxCMOS')] p1: tolerance=20 checknetsindiffpair=FALSE checkdiffpairvsdiffpair=TRUE checkxsignals=TRUE checkothers=TRUE
MatchedLengths "JR TO RESISTOR" [InxSignalClass('j4 TO RESISTOR')] p2: tolerance=20 checknetsindiffpair=FALSE checkdiffpairvsdiffpair=TRUE checkxsignals=TRUE checkothers=TRUE
MatchedLengths "J1 TO RESISTOR" [InxSignalClass('J1 TO RESISTOR')] p3: tolerance=20 checknetsindiffpair=FALSE checkdiffpairvsdiffpair=TRUE checkxsignals=TRUE checkothers=TRUE
MatchedLengths "DAC_DB( 0-7 )" [InxSignalClass('DAC_DB( 0-7 )')] p4: tolerance=5 checknetsindiffpair=TRUE checkdiffpairvsdiffpair=FALSE checkxsignals=FALSE checkothers=FALSE
MatchedLengths "DAC_DA( 0-7 )" [InxSignalClass('DAC_DA( 0-7 )')] p5: tolerance=5 checknetsindiffpair=TRUE checkdiffpairvsdiffpair=FALSE checkxsignals=FALSE checkothers=FALSE
MatchedLengths "ADC_DB( 0-7 )" [InxSignalClass('ADC_DB( 0-7 )')] p6: tolerance=5 checknetsindiffpair=TRUE checkdiffpairvsdiffpair=FALSE checkxsignals=FALSE checkothers=FALSE
MatchedLengths "ADC_DA( 0-7 )" [InxSignalClass('ADC_DA( 0-7 )')] p7: tolerance=5 checknetsindiffpair=TRUE checkdiffpairvsdiffpair=FALSE checkxsignals=FALSE checkothers=FALSE
MatchedLengths DATA [(InDifferentialPairClass('Data Lines'))] p8: tolerance=200 checknetsindiffpair=FALSE checkdiffpairvsdiffpair=TRUE checkxsignals=TRUE checkothers=TRUE
MatchedLengths "FMC+ TO FMC_DATA" [InxSignalClass('FMC+ to FMC_DATA')] p9: tolerance=20 checknetsindiffpair=FALSE checkdiffpairvsdiffpair=TRUE checkxsignals=TRUE checkothers=TRUE
MatchedLengths FPGA_JESD_CONN [InxSignalClass('FPGA_JESD_CONN')] p10: tolerance=20 checknetsindiffpair=FALSE checkdiffpairvsdiffpair=TRUE checkxsignals=TRUE checkothers=TRUE
MinimumAnnularRing MinimumAnnularRing_ThermalPadVias [IsVia and InAnyComponent] p1: minimumring=5.91
MinimumAnnularRing [All] p2: minimumring=5
MinimumSolderMaskSliver MinimumSolderMaskSliver_Logo [InComponentClass('Logo') vs InComponentClass('Logo')] p1: minsoldermaskwidth=0.7
MinimumSolderMaskSliver [All] p2: minsoldermaskwidth=3.94
PlaneConnect [All] p1: planeconnectstyle=Relief reliefexpansion=10 reliefentries=4 reliefconductorwidth=10 reliefairgap=10
PolygonConnect [All] p1: connectstyle=Direct reliefconductorwidth=20 reliefentries=4 polygonreliefangle="90 Angle" airgapwidth=15
RoutingVias ThermalPadVias [IsVia and InAnyComponent] p1: holewidth=7.87 width=19.68 viastyle="Through Hole" minholewidth=7.87 minwidth=19.68 maxholewidth=12.99 maxwidth=23.62
RoutingVias [All] p2: holewidth=12 width=24 viastyle="Through Hole" minholewidth=8 minwidth=18 maxholewidth=20 maxwidth=40
SMDToCorner [All] p1: distance=30000
SilkToSilkClearance [All] p1: silktosilkclearance=5
SilkToSolderMaskClearance SilkscreenOverComponentPads [IsPad] p1: minsilkscreentomaskgap=5 clearancetoexposedcopper=TRUE
SolderMaskExpansion [All] p1: expansion=2.5
Width [All] p1: maxlimit=20 minlimit=3.75 preferedwidth=6.5 toplayer_minwidth=11 toplayer_prefwidth=11 midlayer1_minwidth=0 midlayer1_maxwidth=0 midlayer1_prefwidth=0 midlayer2_minwidth=0 midlayer2_maxwidth=0 midlayer2_prefwidth=0 midlayer3_maxwidth=3.75 midlayer3_prefwidth=3.75 midlayer4_minwidth=4.25 midlayer4_maxwidth=4.25 midlayer4_prefwidth=4.25 midlayer5_minwidth=0 midlayer5_maxwidth=0 midlayer5_prefwidth=0 midlayer6_minwidth=5.5 midlayer6_maxwidth=5.5 midlayer6_prefwidth=5.5 midlayer7_minwidth=0 midlayer7_maxwidth=0 midlayer7_prefwidth=0 midlayer8_minwidth=0 midlayer8_maxwidth=0 midlayer8_prefwidth=0 midlayer9_minwidth=0 midlayer9_maxwidth=0 midlayer9_prefwidth=0 midlayer10_minwidth=6.5 midlayer10_maxwidth=6.5 bottomlayer_minwidth=11 bottomlayer_maxwidth=11 bottomlayer_prefwidth=11 minimp=50.000000 maximp=50.000000 favimp=50.000000
16 further rules are at their usual default settings.

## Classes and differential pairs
differential pair class "J3 TO RESISTOR": 1 2 3 9 10 DIFF FPGA_JESD_CLK_A** FPGA_JESD_CLK_B** FPGA_JESD_SYSREF**
differential pair class "Data Lines": ADC_DA0 ADC_DA1 ADC_DA2 ADC_DA3 ADC_DA4 ADC_DA5 ADC_DA6 ADC_DA7 ADC_DB0 ADC_DB1 ADC_DB2 ADC_DB3 ADC_DB4 ADC_DB5 ADC_DB6 ADC_DB7 DAC_DA0 DAC_DA1 DAC_DA2 DAC_DA3 DAC_DA4 DAC_DA5 DAC_DA6 DAC_DA7 DAC_DB0 DAC_DB1 DAC_DB2 DAC_DB3 DAC_DB4 DAC_DB5 DAC_DB6 DAC_DB7
net class "Data Lines": ADC_DA0_N ADC_DA0_P ADC_DA1_N ADC_DA1_P ADC_DA2_N ADC_DA2_P ADC_DA3_N ADC_DA3_P ADC_DA4_N ADC_DA4_P ADC_DA5_N ADC_DA5_P ADC_DA6_N ADC_DA6_P ADC_DA7_N ADC_DA7_P ADC_DB0_N ADC_DB0_P ADC_DB1_N ADC_DB1_P ADC_DB2_N ADC_DB2_P ADC_DB3_N ADC_DB3_P ADC_DB4_N ADC_DB4_P ADC_DB5_N ADC_DB5_P ADC_DB6_N ADC_DB6_P ADC_DB7_N ADC_DB7_P DAC_DA0_N DAC_DA0_P DAC_DA1_N DAC_DA1_P DAC_DA2_N DAC_DA2_P DAC_DA3_N DAC_DA3_P DAC_DA4_N DAC_DA4_P DAC_DA5_N DAC_DA5_P DAC_DA6_N DAC_DA6_P DAC_DA7_N DAC_DA7_P DAC_DB0_N DAC_DB0_P DAC_DB1_N DAC_DB1_P DAC_DB2_N DAC_DB2_P DAC_DB3_N DAC_DB3_P DAC_DB4_N DAC_DB4_P DAC_DB5_N DAC_DB5_P DAC_DB6_N DAC_DB6_P DAC_DB7_N DAC_DB7_P
component class "TIDA-010131-FMC+ TO FMC_Adapter Card_Sheet3": J2 R19 R39 R45 R46
component class "TIDA-010131-FMC+ TO FMC_Adapter Card_Sheet2": J1 R1 R2 R3 R4 R5 R6 R7 R9 R10 R11 R12 R13 R14 R15 R16 R17 R18 R38 R43 R44 R47 R48
component class "TIDA-010131-FMC+ TO FMC_Adapter Card_Hardware": FID1 FID2 FID3 LBL1 Logo1 Logo2 Logo3 Logo4 ZZ1 ZZ2 ZZ3 ZZ4
component class FiducialMark: FID1 FID2 FID3
component class AssemblyNote: ZZ1 ZZ2 ZZ3 ZZ4
component class Label: LBL1
component class "TIDA-010131-FMC+ TO FMC_Adapter Card_Sheet1": J3 R8 R20 R21 R22 R23 R24 R25 R26 R27 R28 R29 R30 R31 R32 R33 R34 R35 R36 R37 R40 R41 R42
differential pair class 100ohm: 1 2 3 4 5 6 7 8 9 10 ADC_ALT_SYNC ADC_DA0 ADC_DA1 ADC_DA2 ADC_DA3 ADC_DA4 ADC_DA5 ADC_DA6 ADC_DA7 ADC_DB0 ADC_DB1 ADC_DB2 ADC_DB3 ADC_DB4 ADC_DB5 ADC_DB6 ADC_DB7 CLKOUT12 DAC_ALT_SYNC DAC_DA0 DAC_DA1 DAC_DA2 DAC_DA3 DAC_DA4 DAC_DA5 DAC_DA6 DAC_DA7 DAC_DB0 DAC_DB1 DAC_DB2 DAC_DB3 DAC_DB4 DAC_DB5 DAC_DB6 DAC_DB7 DAC_SYNC DIFF DIFF1 DIFF2 FPGA_CLK1 FPGA_CLK2 FPGA_JESD_CLK_A FPGA_JESD_CLK_A* FPGA_JESD_CLK_A** FPGA_JESD_CLK_B FPGA_JESD_CLK_B* FPGA_JESD_CLK_B** FPGA_JESD_CLK_C FPGA_JESD_CLK_D FPGA_JESD_SYSREF FPGA_JESD_SYSREF* FPGA_JESD_SYSREF** GBTCLK1_M2C NewDifferentialPair1 SYNC SYNC_SE
component class "TIDA-010131-FMC+ TO FMC_Adapter Card_Sheet4": J4
net class SYNCBxCMOS: SYNCB0CMOS SYNCB1CMOS SYNCB2CMOS SYNCB3CMOS
differential pair NewDifferentialPair1: +NetJ3_33 -NetJ3_31
differential pair ADC_DB7: +ADC_DB7_N -ADC_DB7_P
differential pair ADC_DB6: +ADC_DB6_N -ADC_DB6_P
differential pair ADC_DB5: +ADC_DB5_N -ADC_DB5_P
differential pair ADC_DB4: +ADC_DB4_N -ADC_DB4_P
differential pair ADC_DB3: +ADC_DB3_N -ADC_DB3_P
differential pair ADC_DB2: +ADC_DB2_N -ADC_DB2_P
differential pair ADC_DB1: +ADC_DB1_N -ADC_DB1_P
differential pair ADC_DB0: +ADC_DB0_N -ADC_DB0_P
differential pair ADC_DA7: +ADC_DA7_N -ADC_DA7_P
differential pair ADC_DA6: +ADC_DA6_N -ADC_DA6_P
differential pair ADC_DA5: +ADC_DA5_N -ADC_DA5_P
differential pair ADC_DA4: +ADC_DA4_N -ADC_DA4_P
differential pair ADC_DA3: +ADC_DA3_N -ADC_DA3_P
differential pair ADC_DA2: +ADC_DA2_N -ADC_DA2_P
differential pair ADC_DA1: +ADC_DA1_N -ADC_DA1_P
differential pair ADC_DA0: +ADC_DA0_N -ADC_DA0_P
differential pair 5: +NetJ1_Z20 -NetJ1_Z21
differential pair 4: +NetJ1_B21 -NetJ1_B20
differential pair 3: +NetJ3_36 -NetJ3_34
differential pair 2: +NetJ3_12 -NetJ3_10
differential pair 1: +NetJ3_44 -NetJ3_42
differential pair FPGA_JESD_SYSREF*: +NetJ1_G9 -NetJ1_G10
differential pair FPGA_JESD_CLK_B*: +NetJ1_G6 -NetJ1_G7
differential pair FPGA_JESD_CLK_A*: +NetJ1_D4 -NetJ1_D5
differential pair SYNC: +ADC_SYNC_P -ADC_SYNC_N
differential pair FPGA_JESD_SYSREF: +FPGA_JESD_SYSREFP -FPGA_JESD_SYSREFM
differential pair FPGA_JESD_CLK_B: +FPGA_JESD_CLK_B_P -FPGA_JESD_CLK_B_N
differential pair FPGA_JESD_CLK_A: +FPGA_JESD_CLK_A_P -FPGA_JESD_CLK_A_N
differential pair FPGA_JESD_SYSREF**: +NetJ3_25 -NetJ3_23
differential pair FPGA_JESD_CLK_B**: +NetJ3_17 -NetJ3_15
differential pair FPGA_JESD_CLK_A**: +NetJ3_9 -NetJ3_7
differential pair CLKOUT12: +DCLKOUT12_P -DCLKOUT12_N
differential pair FPGA_CLK2: +FPGA_CLK2_P -FPGA_CLK2_N
differential pair FPGA_JESD_CLK_C: +FPGA_JESD_CLK_C_P -FPGA_JESD_CLK_C_N
differential pair DAC_DA0: +DAC_DA0_P -DAC_DA0_N
differential pair FPGA_CLK1: +FPGA_CLK1_P -FPGA_CLK1_N
differential pair FPGA_JESD_CLK_D: +FPGA_JESD_CLK_D_P -FPGA_JESD_CLK_D_N
differential pair DAC_DB2: +DAC_DB2_P -DAC_DB2_N
differential pair DAC_SYNC: +DAC_SYNC_P -DAC_SYNC_N
differential pair DAC_ALT_SYNC: +DAC_ALT_SYNC_P -DAC_ALT_SYNC_N
differential pair GBTCLK1_M2C: +GBTCLK1_M2C_P -GBTCLK1_M2C_N
differential pair DAC_DA1: +DAC_DA1_P -DAC_DA1_N
differential pair DAC_DB6: +DAC_DB6_P -DAC_DB6_N
differential pair DAC_DB0: +DAC_DB0_P -DAC_DB0_N
differential pair DAC_DB3: +DAC_DB3_P -DAC_DB3_N
differential pair DAC_DA2: +DAC_DA2_P -DAC_DA2_N
differential pair DAC_DB7: +DAC_DB7_P -DAC_DB7_N
differential pair DAC_DB1: +DAC_DB1_P -DAC_DB1_N
differential pair DAC_DB4: +DAC_DB4_P -DAC_DB4_N
differential pair DAC_DA3: +DAC_DA3_P -DAC_DA3_N
differential pair ADC_ALT_SYNC: +ADC_ALT_SYNC_N -ADC_ALT_SYNC_P
differential pair DAC_DA7: +DAC_DA7_P -DAC_DA7_N
differential pair DAC_DA4: +DAC_DA4_P -DAC_DA4_N
differential pair DAC_DA6: +DAC_DA6_P -DAC_DA6_N
differential pair DAC_DA5: +DAC_DA5_P -DAC_DA5_N
differential pair DAC_DB5: +DAC_DB5_P -DAC_DB5_N
differential pair 6: +NetJ1_K4 -NetJ1_K5
differential pair 7: +NetJ1_H5 -NetJ1_H4
differential pair 8: +NetJ1_G2 -NetJ1_G3
differential pair 9: +NetJ3_28 -NetJ3_26
differential pair 10: +NetJ3_20 -NetJ3_18
differential pair SYNC_SE: +SYNC_SE_IN -SYNC_SE_IN_N
differential pair DIFF: +NetJ3_50 -NetJ3_52
differential pair DIFF1: +NetJ1_J2 -NetJ1_J3
differential pair DIFF2: +NetJ1_G12 -NetJ1_G13

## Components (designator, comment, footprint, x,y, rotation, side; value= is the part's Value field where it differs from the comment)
FID1 "Fiducial" Fiducial10-20 2697.09,74.5 r90 top
FID2 "Fiducial" Fiducial10-20 888,2263 r90 top
FID3 "Fiducial" Fiducial10-20 2086,2295 r90 top
J1 "ASP-184329-01" Samtec_ASP-184329-01 410,1187.5 r270 top locked
J2 "ASP-134488-01" Samtec_ASP-134488-01 2433,1187.5 r180 bottom locked
J3 "QSH-030-01-L-D-A" Samtec_QSH-030-01-X-D-A 1591.33,218.7 r270 top locked
J4 "ASP-184330-01" ASP-184330-01 2433,1187.5 r270 bottom locked
LBL1 "Size: 0.65\" x 0.20 \"" Label_650x200 1615,372 r180 bottom
Logo1 "ESD Susceptible" ESD_Overlay_SMALL 1451,2173 r0 top
Logo2 "Pb-Free Symbol" Pb-Free_Overlay_Small 1982,2195 r0 top
Logo3 "FCC disclaimer" FCC_disclaimer 3112,2806 r180 top
Logo4 "WEEE logo" WEEE_Minimum 1178.14,2114 r0 top
R1 "ERJ-1GN0R00C" 0201 1637.75,914.53 r90 bottom value=0
R2 "ERJ-1GN0R00C" 0201 1637.75,828.03 r270 bottom value=0
R3 "ERJ-1GN0R00C" 0201 1637.6,761.5 r270 bottom value=0
R4 "ERJ-1GN0R00C" 0201 1637.6,680.6 r90 bottom value=0
R5 "ERJ-1GN0R00C" 0201 1335.93,715.98 r270 bottom value=0
R6 "ERJ-1GN0R00C" 0201 1335.93,637.02 r90 bottom value=0
R7 "CRCW04020000Z0ED" 0402 1379,526.62 r270 top value=0
R8 "CRCW04020000Z0ED" 0402 1379,479.86 r270 top value=0
R9 "ERJ-1GN0R00C" 0201 855.49,502.49 r90 top value=0
R10 "ERJ-1GN0R00C" 0201 855.5,425.51 r270 top value=0
R11 "ERJ-1GN0R00C" 0201 1426,909.01 r270 top value=0
R12 "ERJ-1GN0R00C" 0201 1426,832.02 r90 top value=0
R13 "ERJ-1GN0R00C" 0201 1255.99,908.99 r90 top value=0
R14 "ERJ-1GN0R00C" 0201 1181,591.99 r90 top value=0
R15 "ERJ-1GN0R00C" 0201 1255.99,832.01 r270 top value=0
R16 "ERJ-1GN0R00C" 0201 1181,517.01 r270 top value=0
R17 "ERJ-1GN0R00C" 0201 1025.25,500.96 r90 top value=0
R18 "ERJ-1GN0R00C" 0201 1025.25,425.97 r270 top value=0
R19 "CRCW04020000Z0ED" 0402 1533,491.62 r0 top value=0
R20 "ERJ-1GN0R00C" 0201 1624.15,843.78 r180 bottom value=0
R21 "ERJ-1GN0R00C" 0201 1322.31,650.23 r180 bottom value=0
R22 "ERJ-1GN0R00C" 0201 1624.15,898.78 r180 bottom value=0
R23 "ERJ-1GN0R00C" 0201 1322.31,700.23 r180 bottom value=0
R24 "ERJ-1GN0R00C" 0201 1622.6,696.35 r180 bottom value=0
R25 "CRCW04020000Z0ED" 0402 1562,465.62 r270 top value=0
R26 "ERJ-1GN0R00C" 0201 1622.6,746.35 r180 bottom value=0
R27 "CRCW04020000Z0ED" 0402 1506,465.62 r270 top value=0
R28 "ERJ-1GN0R00C" 0201 842.51,439.5 r0 top value=0
R29 "ERJ-1GN0R00C" 0201 842.5,489.5 r0 top value=0
R30 "ERJ-1GN0R00C" 0201 1413.01,846.02 r0 top value=0
R31 "ERJ-1GN0R00C" 0201 1413.01,896.02 r0 top value=0
R32 "ERJ-1GN0R00C" 0201 1243,846 r0 top value=0
R33 "ERJ-1GN0R00C" 0201 1243,896 r0 top value=0
R34 "ERJ-1GN0R00C" 0201 1168.01,530 r0 top value=0
R35 "ERJ-1GN0R00C" 0201 1168.01,579 r0 top value=0
R36 "ERJ-1GN0R00C" 0201 1012.26,438.96 r0 top value=0
R37 "ERJ-1GN0R00C" 0201 1012.26,487.96 r0 top value=0
R38 "CRCW04020000Z0ED" 0402 1299,526.62 r270 top value=0
R39 "CRCW04020000Z0ED" 0402 1533,542.62 r0 top value=0
R40 "CRCW04020000Z0ED" 0402 1299,479.86 r270 top value=0
R41 "ERJ-1GN0R00C" 0201 1109.99,346 r0 bottom value=0
R42 "ERJ-1GN0R00C" 0201 1109.99,385 r0 bottom value=0
R43 "ERJ-1GN0R00C" 0201 1122.98,333.01 r90 bottom value=0
R44 "ERJ-1GN0R00C" 0201 1122.98,397.99 r270 bottom value=0
R45 "CRCW04020000Z0ED" 0402 1506,566.24 r270 top value=0
R46 "CRCW04020000Z0ED" 0402 1562,566.24 r270 top value=0
R47 "CRCW04020000Z0ED" 0402 1422,1580 r0 top value=0
R48 "CRCW04020000Z0ED" 0402 1422,1529 r0 top value=0
ZZ1 "This Assembly Note is for PCB labels only" AssemblyNoteLabel 391,-425.45 r0 top
ZZ2 "These assemblies are ESD sensitive, ESD precautions shall be observed." AssemblyNote 387,-479.45 r0 top
ZZ3 "These assemblies must be clean and free from flux and all contaminants. Use of no clean flux is not acceptable." AssemblyNote 391,-549.45 r0 top
ZZ4 "These assemblies must comply with workmanship standards IPC-A-610 Class 2, unless otherwise specified." AssemblyNote 399,-619.45 r0 top

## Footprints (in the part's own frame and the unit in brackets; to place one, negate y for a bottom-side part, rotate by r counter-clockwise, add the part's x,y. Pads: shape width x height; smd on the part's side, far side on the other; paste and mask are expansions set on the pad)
0201 [mm] "Data from Kemet datasheet CC101_COM dated 7/28/11"
  rect 0.46x0.42 smd mask+0.048: 1(-0.33,0) 2(0.33,0)
  body extent -0.31,-0.16 0.31,0.16, height 0.26
0402 [mm] "0402 from SM-752 data"
  rect 0.8x0.6 smd: 1(-0.6,0) 2(0.6,0)
  silkscreen extent -1.22,-0.52 1.22,0.52, body extent -0.55,-0.3 0.55,0.3, height 0.6
ASP-184330-01 [mil]
  round 25 smd paste+5 mask+2: A1(-975,-225) A2(-925,-225) A3(-875,-225) A4(-825,-225) A5(-775,-225) A6(-725,-225) A7(-675,-225) A8(-625,-225) A9(-575,-225) A10(-525,-225) A11(-475,-225) A12(-425,-225) A13(-375,-225) A14(-325,-225) A15(-275,-225) A16(-225,-225) A17(-175,-225) A18(-125,-225) A19(-75,-225) A20(-25,-225) A21(25,-225) A22(75,-225) A23(125,-225) A24(175,-225) A25(225,-225) A26(275,-225) A27(325,-225) A28(375,-225) A29(425,-225) A30(475,-225) A31(525,-225) A32(575,-225) A33(625,-225) A34(675,-225) A35(725,-225) A36(775,-225) A37(825,-225) A38(875,-225) A39(925,-225) A40(975,-225) B1(-975,-175) B2(-925,-175) B3(-875,-175) B4(-825,-175) B5(-775,-175) B6(-725,-175) B7(-675,-175) B8(-625,-175) B9(-575,-175) B10(-525,-175) B11(-475,-175) B12(-425,-175) B13(-375,-175) B14(-325,-175) B15(-275,-175) B16(-225,-175) B17(-175,-175) B18(-125,-175) B19(-75,-175) B20(-25,-175) B21(25,-175) B22(75,-175) B23(125,-175) B24(175,-175) B25(225,-175) B26(275,-175) B27(325,-175) B28(375,-175) B29(425,-175) B30(475,-175) B31(525,-175) B32(575,-175) B33(625,-175) B34(675,-175) B35(725,-175) B36(775,-175) B37(825,-175) B38(875,-175) B39(925,-175) B40(975,-175) C1(-975,-125) C2(-925,-125) C3(-875,-125) C4(-825,-125) C5(-775,-125) C6(-725,-125) C7(-675,-125) C8(-625,-125) C9(-575,-125) C10(-525,-125) C11(-475,-125) C12(-425,-125) C13(-375,-125) C14(-325,-125) C15(-275,-125) C16(-225,-125) C17(-175,-125) C18(-125,-125) C19(-75,-125) C20(-25,-125) C21(25,-125) C22(75,-125) C23(125,-125) C24(175,-125) C25(225,-125) C26(275,-125) C27(325,-125) C28(375,-125) C29(425,-125) C30(475,-125) C31(525,-125) C32(575,-125) C33(625,-125) C34(675,-125) C35(725,-125) C36(775,-125) C37(825,-125) C38(875,-125) C39(925,-125) C40(975,-125) D1(-975,-75) D2(-925,-75) D3(-875,-75) D4(-825,-75) D5(-775,-75) D6(-725,-75) D7(-675,-75) D8(-625,-75) D9(-575,-75) D10(-525,-75) D11(-475,-75) D12(-425,-75) D13(-375,-75) D14(-325,-75) D15(-275,-75) D16(-225,-75) D17(-175,-75) D18(-125,-75) D19(-75,-75) D20(-25,-75) D21(25,-75) D22(75,-75) D23(125,-75) D24(175,-75) D25(225,-75) D26(275,-75) D27(325,-75) D28(375,-75) D29(425,-75) D30(475,-75) D31(525,-75) D32(575,-75) D33(625,-75) D34(675,-75) D35(725,-75) D36(775,-75) D37(825,-75) D38(875,-75) D39(925,-75) D40(975,-75) E1(-975,-25) E2(-925,-25) E3(-875,-25) E4(-825,-25) E5(-775,-25) E6(-725,-25) E7(-675,-25) E8(-625,-25) E9(-575,-25) E10(-525,-25) E11(-475,-25) E12(-425,-25) E13(-375,-25) E14(-325,-25) E15(-275,-25) E16(-225,-25) E17(-175,-25) E18(-125,-25) E19(-75,-25) E20(-25,-25) E21(25,-25) E22(75,-25) E23(125,-25) E24(175,-25) E25(225,-25) E26(275,-25) E27(325,-25) E28(375,-25) E29(425,-25) E30(475,-25) E31(525,-25) E32(575,-25) E33(625,-25) E34(675,-25) E35(725,-25) E36(775,-25) E37(825,-25) E38(875,-25) E39(925,-25) E40(975,-25) F1(-975,25) F2(-925,25) F3(-875,25) F4(-825,25) F5(-775,25) F6(-725,25) F7(-675,25) F8(-625,25) F9(-575,25) F10(-525,25) F11(-475,25) F12(-425,25) F13(-375,25) F14(-325,25) F15(-275,25) F16(-225,25) F17(-175,25) F18(-125,25) F19(-75,25) F20(-25,25) F21(25,25) F22(75,25) F23(125,25) F24(175,25) F25(225,25) F26(275,25) F27(325,25) F28(375,25) F29(425,25) F30(475,25) F31(525,25) F32(575,25) F33(625,25) F34(675,25) F35(725,25) F36(775,25) F37(825,25) F38(875,25) F39(925,25) F40(975,25) G1(-975,75) G2(-925,75) G3(-875,75) G4(-825,75) G5(-775,75) G6(-725,75) G7(-675,75) G8(-625,75) G9(-575,75) G10(-525,75) G11(-475,75) G12(-425,75) G13(-375,75) G14(-325,75) G15(-275,75) G16(-225,75) G17(-175,75) G18(-125,75) G19(-75,75) G20(-25,75) G21(25,75) G22(75,75) G23(125,75) G24(175,75) G25(225,75) G26(275,75) G27(325,75) G28(375,75) G29(425,75) G30(475,75) G31(525,75) G32(575,75) G33(625,75) G34(675,75) G35(725,75) G36(775,75) G37(825,75) G38(875,75) G39(925,75) G40(975,75) H1(-975,125) H2(-925,125) H3(-875,125) H4(-825,125) H5(-775,125) H6(-725,125) H7(-675,125) H8(-625,125) H9(-575,125) H10(-525,125) H11(-475,125) H12(-425,125) H13(-375,125) H14(-325,125) H15(-275,125) H16(-225,125) H17(-175,125) H18(-125,125) H19(-75,125) H20(-25,125) H21(25,125) H22(75,125) H23(125,125) H24(175,125) H25(225,125) H26(275,125) H27(325,125) H28(375,125) H29(425,125) H30(475,125) H31(525,125) H32(575,125) H33(625,125) H34(675,125) H35(725,125) H36(775,125) H37(825,125) H38(875,125) H39(925,125) H40(975,125) J1(-975,175) J2(-925,175) J3(-875,175) J4(-825,175) J5(-775,175) J6(-725,175) J7(-675,175) J8(-625,175) J9(-575,175) J10(-525,175) J11(-475,175) J12(-425,175) J13(-375,175) J14(-325,175) J15(-275,175) J16(-225,175) J17(-175,175) J18(-125,175) J19(-75,175) J20(-25,175) J21(25,175) J22(75,175) J23(125,175) J24(175,175) J25(225,175) J26(275,175) J27(325,175) J28(375,175) J29(425,175) J30(475,175) J31(525,175) J32(575,175) J33(625,175) J34(675,175) J35(725,175) J36(775,175) J37(825,175) J38(875,175) J39(925,175) J40(975,175) K1(-975,225) K2(-925,225) K3(-875,225) K4(-825,225) K5(-775,225) K6(-725,225) K7(-675,225) K8(-625,225) K9(-575,225) K10(-525,225) K11(-475,225) K12(-425,225) K13(-375,225) K14(-325,225) K15(-275,225) K16(-225,225) K17(-175,225) K18(-125,225) K19(-75,225) K20(-25,225) K21(25,225) K22(75,225) K23(125,225) K24(175,225) K25(225,225) K26(275,225) K27(325,225) K28(375,225) K29(425,225) K30(475,225) K31(525,225) K32(575,225) K33(625,225) K34(675,225) K35(725,225) K36(775,225) K37(825,225) K38(875,225) K39(925,225) K40(975,225) L1(-975,275) L2(-925,275) L3(-875,275) L4(-825,275) L5(-775,275) L6(-725,275) L7(-675,275) L8(-625,275) L9(-575,275) L10(-525,275) L11(-475,275) L12(-425,275) L13(-375,275) L14(-325,275) L15(-275,275) L16(-225,275) L17(-175,275) L18(-125,275) L19(-75,275) L20(-25,275) L21(25,275) L22(75,275) L23(125,275) L24(175,275) L25(225,275) L26(275,275) L27(325,275) L28(375,275) L29(425,275) L30(475,275) L31(525,275) L32(575,275) L33(625,275) L34(675,275) L35(725,275) L36(775,275) L37(825,275) L38(875,275) L39(925,275) L40(975,275) M1(-975,325) M2(-925,325) M3(-875,325) M4(-825,325) M5(-775,325) M6(-725,325) M7(-675,325) M8(-625,325) M9(-575,325) M10(-525,325) M11(-475,325) M12(-425,325) M13(-375,325) M14(-325,325) M15(-275,325) M16(-225,325) M17(-175,325) M18(-125,325) M19(-75,325) M20(-25,325) M21(25,325) M22(75,325) M23(125,325) M24(175,325) M25(225,325) M26(275,325) M27(325,325) M28(375,325) M29(425,325) M30(475,325) M31(525,325) M32(575,325) M33(625,325) M34(675,325) M35(725,325) M36(775,325) M37(825,325) M38(875,325) M39(925,325) M40(975,325) Y1(-975,-325) Y2(-925,-325) Y3(-875,-325) Y4(-825,-325) Y5(-775,-325) Y6(-725,-325) Y7(-675,-325) Y8(-625,-325) Y9(-575,-325) Y10(-525,-325) Y11(-475,-325) Y12(-425,-325) Y13(-375,-325) Y14(-325,-325) Y15(-275,-325) Y16(-225,-325) Y17(-175,-325) Y18(-125,-325) Y19(-75,-325) Y20(-25,-325) Y21(25,-325) Y22(75,-325) Y23(125,-325) Y24(175,-325) Y25(225,-325) Y26(275,-325) Y27(325,-325) Y28(375,-325) Y29(425,-325) Y30(475,-325) Y31(525,-325) Y32(575,-325) Y33(625,-325) Y34(675,-325) Y35(725,-325) Y36(775,-325) Y37(825,-325) Y38(875,-325) Y39(925,-325) Y40(975,-325) Z1(-975,-275) Z2(-925,-275) Z3(-875,-275) Z4(-825,-275) Z5(-775,-275) Z6(-725,-275) Z7(-675,-275) Z8(-625,-275) Z9(-575,-275) Z10(-525,-275) Z11(-475,-275) Z12(-425,-275) Z13(-375,-275) Z14(-325,-275) Z15(-275,-275) Z16(-225,-275) Z17(-175,-275) Z18(-125,-275) Z19(-75,-275) Z20(-25,-275) Z21(25,-275) Z22(75,-275) Z23(125,-275) Z24(175,-275) Z25(225,-275) Z26(275,-275) Z27(325,-275) Z28(375,-275) Z29(425,-275) Z30(475,-275) Z31(525,-275) Z32(575,-275) Z33(625,-275) Z34(675,-275) Z35(725,-275) Z36(775,-275) Z37(825,-275) Z38(875,-275) Z39(925,-275) Z40(975,-275)
  round 50 hole 50 unplated mask+10: MH1(-1070.5,0) MH2(1070.5,120)
  silkscreen extent -1153,-409 1118,409
AssemblyNote [mil] "Assembly Note"
AssemblyNoteLabel [mil] "Assembly Note for PCB Labels"
ESD_Overlay_SMALL [mil]
  silkscreen extent -62,-48 64,61
FCC_disclaimer [mil]
Fiducial10-20 [mm]
  round 1 smd mask+0.5: 1(0,0)
  L1_Top Layer keep-out circle w1.178: c0,0 r0.5
Label_650x200 [mil] "Thermal Transfer Label"
  round 1 on Mech14: 0(0,0)
  silkscreen extent -325,-100 325,100, body extent -325,-100 325,100, height 1
Pb-Free_Overlay_Small [mil]
  silkscreen extent -46,-46 46,46
Samtec_ASP-134488-01 [mm] "Connector, 1.27mm, 40x10, SMT"
  round 0.64 smd paste+0.125: A1(-5.715,24.765) A2(-5.715,23.495) A3(-5.715,22.225) A4(-5.715,20.955) A5(-5.715,19.685) A6(-5.715,18.415) A7(-5.715,17.145) A8(-5.715,15.875) A9(-5.715,14.605) A10(-5.715,13.335) A11(-5.715,12.065) A12(-5.715,10.795) A13(-5.715,9.525) A14(-5.715,8.255) A15(-5.715,6.985) A16(-5.715,5.715) A17(-5.715,4.445) A18(-5.715,3.175) A19(-5.715,1.905) A20(-5.715,0.635) A21(-5.715,-0.635) A22(-5.715,-1.905) A23(-5.715,-3.175) A24(-5.715,-4.445) A25(-5.715,-5.715) A26(-5.715,-6.985) A27(-5.715,-8.255) A28(-5.715,-9.525) A29(-5.715,-10.795) A30(-5.715,-12.065) A31(-5.715,-13.335) A32(-5.715,-14.605) A33(-5.715,-15.875) A34(-5.715,-17.145) A35(-5.715,-18.415) A36(-5.715,-19.685) A37(-5.715,-20.955) A38(-5.715,-22.225) A39(-5.715,-23.495) A40(-5.715,-24.765) B1(-4.445,24.765) B2(-4.445,23.495) B3(-4.445,22.225) B4(-4.445,20.955) B5(-4.445,19.685) B6(-4.445,18.415) B7(-4.445,17.145) B8(-4.445,15.875) B9(-4.445,14.605) B10(-4.445,13.335) B11(-4.445,12.065) B12(-4.445,10.795) B13(-4.445,9.525) B14(-4.445,8.255) B15(-4.445,6.985) B16(-4.445,5.715) B17(-4.445,4.445) B18(-4.445,3.175) B19(-4.445,1.905) B20(-4.445,0.635) B21(-4.445,-0.635) B22(-4.445,-1.905) B23(-4.445,-3.175) B24(-4.445,-4.445) B25(-4.445,-5.715) B26(-4.445,-6.985) B27(-4.445,-8.255) B28(-4.445,-9.525) B29(-4.445,-10.795) B30(-4.445,-12.065) B31(-4.445,-13.335) B32(-4.445,-14.605) B33(-4.445,-15.875) B34(-4.445,-17.145) B35(-4.445,-18.415) B36(-4.445,-19.685) B37(-4.445,-20.955) B38(-4.445,-22.225) B39(-4.445,-23.495) B40(-4.445,-24.765) C1(-3.175,24.765) C2(-3.175,23.495) C3(-3.175,22.225) C4(-3.175,20.955) C5(-3.175,19.685) C6(-3.175,18.415) C7(-3.175,17.145) C8(-3.175,15.875) C9(-3.175,14.605) C10(-3.175,13.335) C11(-3.175,12.065) C12(-3.175,10.795) C13(-3.175,9.525) C14(-3.175,8.255) C15(-3.175,6.985) C16(-3.175,5.715) C17(-3.175,4.445) C18(-3.175,3.175) C19(-3.175,1.905) C20(-3.175,0.635) C21(-3.175,-0.635) C22(-3.175,-1.905) C23(-3.175,-3.175) C24(-3.175,-4.445) C25(-3.175,-5.715) C26(-3.175,-6.985) C27(-3.175,-8.255) C28(-3.175,-9.525) C29(-3.175,-10.795) C30(-3.175,-12.065) C31(-3.175,-13.335) C32(-3.175,-14.605) C33(-3.175,-15.875) C34(-3.175,-17.145) C35(-3.175,-18.415) C36(-3.175,-19.685) C37(-3.175,-20.955) C38(-3.175,-22.225) C39(-3.175,-23.495) C40(-3.175,-24.765) D1(-1.905,24.765) D2(-1.905,23.495) D3(-1.905,22.225) D4(-1.905,20.955) D5(-1.905,19.685) D6(-1.905,18.415) D7(-1.905,17.145) D8(-1.905,15.875) D9(-1.905,14.605) D10(-1.905,13.335) D11(-1.905,12.065) D12(-1.905,10.795) D13(-1.905,9.525) D14(-1.905,8.255) D15(-1.905,6.985) D16(-1.905,5.715) D17(-1.905,4.445) D18(-1.905,3.175) D19(-1.905,1.905) D20(-1.905,0.635) D21(-1.905,-0.635) D22(-1.905,-1.905) D23(-1.905,-3.175) D24(-1.905,-4.445) D25(-1.905,-5.715) D26(-1.905,-6.985) D27(-1.905,-8.255) D28(-1.905,-9.525) D29(-1.905,-10.795) D30(-1.905,-12.065) D31(-1.905,-13.335) D32(-1.905,-14.605) D33(-1.905,-15.875) D34(-1.905,-17.145) D35(-1.905,-18.415) D36(-1.905,-19.685) D37(-1.905,-20.955) D38(-1.905,-22.225) D39(-1.905,-23.495) D40(-1.905,-24.765) E1(-0.635,24.765) E2(-0.635,23.495) E3(-0.635,22.225) E4(-0.635,20.955) E5(-0.635,19.685) E6(-0.635,18.415) E7(-0.635,17.145) E8(-0.635,15.875) E9(-0.635,14.605) E10(-0.635,13.335) E11(-0.635,12.065) E12(-0.635,10.795) E13(-0.635,9.525) E14(-0.635,8.255) E15(-0.635,6.985) E16(-0.635,5.715) E17(-0.635,4.445) E18(-0.635,3.175) E19(-0.635,1.905) E20(-0.635,0.635) E21(-0.635,-0.635) E22(-0.635,-1.905) E23(-0.635,-3.175) E24(-0.635,-4.445) E25(-0.635,-5.715) E26(-0.635,-6.985) E27(-0.635,-8.255) E28(-0.635,-9.525) E29(-0.635,-10.795) E30(-0.635,-12.065) E31(-0.635,-13.335) E32(-0.635,-14.605) E33(-0.635,-15.875) E34(-0.635,-17.145) E35(-0.635,-18.415) E36(-0.635,-19.685) E37(-0.635,-20.955) E38(-0.635,-22.225) E39(-0.635,-23.495) E40(-0.635,-24.765) F1(0.635,24.765) F2(0.635,23.495) F3(0.635,22.225) F4(0.635,20.955) F5(0.635,19.685) F6(0.635,18.415) F7(0.635,17.145) F8(0.635,15.875) F9(0.635,14.605) F10(0.635,13.335) F11(0.635,12.065) F12(0.635,10.795) F13(0.635,9.525) F14(0.635,8.255) F15(0.635,6.985) F16(0.635,5.715) F17(0.635,4.445) F18(0.635,3.175) F19(0.635,1.905) F20(0.635,0.635) F21(0.635,-0.635) F22(0.635,-1.905) F23(0.635,-3.175) F24(0.635,-4.445) F25(0.635,-5.715) F26(0.635,-6.985) F27(0.635,-8.255) F28(0.635,-9.525) F29(0.635,-10.795) F30(0.635,-12.065) F31(0.635,-13.335) F32(0.635,-14.605) F33(0.635,-15.875) F34(0.635,-17.145) F35(0.635,-18.415) F36(0.635,-19.685) F37(0.635,-20.955) F38(0.635,-22.225) F39(0.635,-23.495) F40(0.635,-24.765) G1(1.905,24.765) G2(1.905,23.495) G3(1.905,22.225) G4(1.905,20.955) G5(1.905,19.685) G6(1.905,18.415) G7(1.905,17.145) G8(1.905,15.875) G9(1.905,14.605) G10(1.905,13.335) G11(1.905,12.065) G12(1.905,10.795) G13(1.905,9.525) G14(1.905,8.255) G15(1.905,6.985) G16(1.905,5.715) G17(1.905,4.445) G18(1.905,3.175) G19(1.905,1.905) G20(1.905,0.635) G21(1.905,-0.635) G22(1.905,-1.905) G23(1.905,-3.175) G24(1.905,-4.445) G25(1.905,-5.715) G26(1.905,-6.985) G27(1.905,-8.255) G28(1.905,-9.525) G29(1.905,-10.795) G30(1.905,-12.065) G31(1.905,-13.335) G32(1.905,-14.605) G33(1.905,-15.875) G34(1.905,-17.145) G35(1.905,-18.415) G36(1.905,-19.685) G37(1.905,-20.955) G38(1.905,-22.225) G39(1.905,-23.495) G40(1.905,-24.765) H1(3.175,24.765) H2(3.175,23.495) H3(3.175,22.225) H4(3.175,20.955) H5(3.175,19.685) H6(3.175,18.415) H7(3.175,17.145) H8(3.175,15.875) H9(3.175,14.605) H10(3.175,13.335) H11(3.175,12.065) H12(3.175,10.795) H13(3.175,9.525) H14(3.175,8.255) H15(3.175,6.985) H16(3.175,5.715) H17(3.175,4.445) H18(3.175,3.175) H19(3.175,1.905) H20(3.175,0.635) H21(3.175,-0.635) H22(3.175,-1.905) H23(3.175,-3.175) H24(3.175,-4.445) H25(3.175,-5.715) H26(3.175,-6.985) H27(3.175,-8.255) H28(3.175,-9.525) H29(3.175,-10.795) H30(3.175,-12.065) H31(3.175,-13.335) H32(3.175,-14.605) H33(3.175,-15.875) H34(3.175,-17.145) H35(3.175,-18.415) H36(3.175,-19.685) H37(3.175,-20.955) H38(3.175,-22.225) H39(3.175,-23.495) H40(3.175,-24.765) J1(4.445,24.765) J2(4.445,23.495) J3(4.445,22.225) J4(4.445,20.955) J5(4.445,19.685) J6(4.445,18.415) J7(4.445,17.145) J8(4.445,15.875) J9(4.445,14.605) J10(4.445,13.335) J11(4.445,12.065) J12(4.445,10.795) J13(4.445,9.525) J14(4.445,8.255) J15(4.445,6.985) J16(4.445,5.715) J17(4.445,4.445) J18(4.445,3.175) J19(4.445,1.905) J20(4.445,0.635) J21(4.445,-0.635) J22(4.445,-1.905) J23(4.445,-3.175) J24(4.445,-4.445) J25(4.445,-5.715) J26(4.445,-6.985) J27(4.445,-8.255) J28(4.445,-9.525) J29(4.445,-10.795) J30(4.445,-12.065) J31(4.445,-13.335) J32(4.445,-14.605) J33(4.445,-15.875) J34(4.445,-17.145) J35(4.445,-18.415) J36(4.445,-19.685) J37(4.445,-20.955) J38(4.445,-22.225) J39(4.445,-23.495) J40(4.445,-24.765) K1(5.715,24.765) K2(5.715,23.495) K3(5.715,22.225) K4(5.715,20.955) K5(5.715,19.685) K6(5.715,18.415) K7(5.715,17.145) K8(5.715,15.875) K9(5.715,14.605) K10(5.715,13.335) K11(5.715,12.065) K12(5.715,10.795) K13(5.715,9.525) K14(5.715,8.255) K15(5.715,6.985) K16(5.715,5.715) K17(5.715,4.445) K18(5.715,3.175) K19(5.715,1.905) K20(5.715,0.635) K21(5.715,-0.635) K22(5.715,-1.905) K23(5.715,-3.175) K24(5.715,-4.445) K25(5.715,-5.715) K26(5.715,-6.985) K27(5.715,-8.255) K28(5.715,-9.525) K29(5.715,-10.795) K30(5.715,-12.065) K31(5.715,-13.335) K32(5.715,-14.605) K33(5.715,-15.875) K34(5.715,-17.145) K35(5.715,-18.415) K36(5.715,-19.685) K37(5.715,-20.955) K38(5.715,-22.225) K39(5.715,-23.495) K40(5.715,-24.765)
  round 1.27 hole 1.27 unplated mask+0.127: MH1(0,27.19) MH2(3.05,-27.19)
  silkscreen extent -7.65,-27.89 7.65,28.78, body extent -7.34,-27.89 7.34,28.78, height 7.11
